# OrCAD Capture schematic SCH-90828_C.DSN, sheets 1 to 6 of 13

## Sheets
1 01 COVER: title: FRDM-MCXN236; rev: C; company: NXP Semiconductors; note: SCH-90828, PDF: SPF-90828; note: 6501 William Cannon Drive West; note: Austin, TX 78735-8598
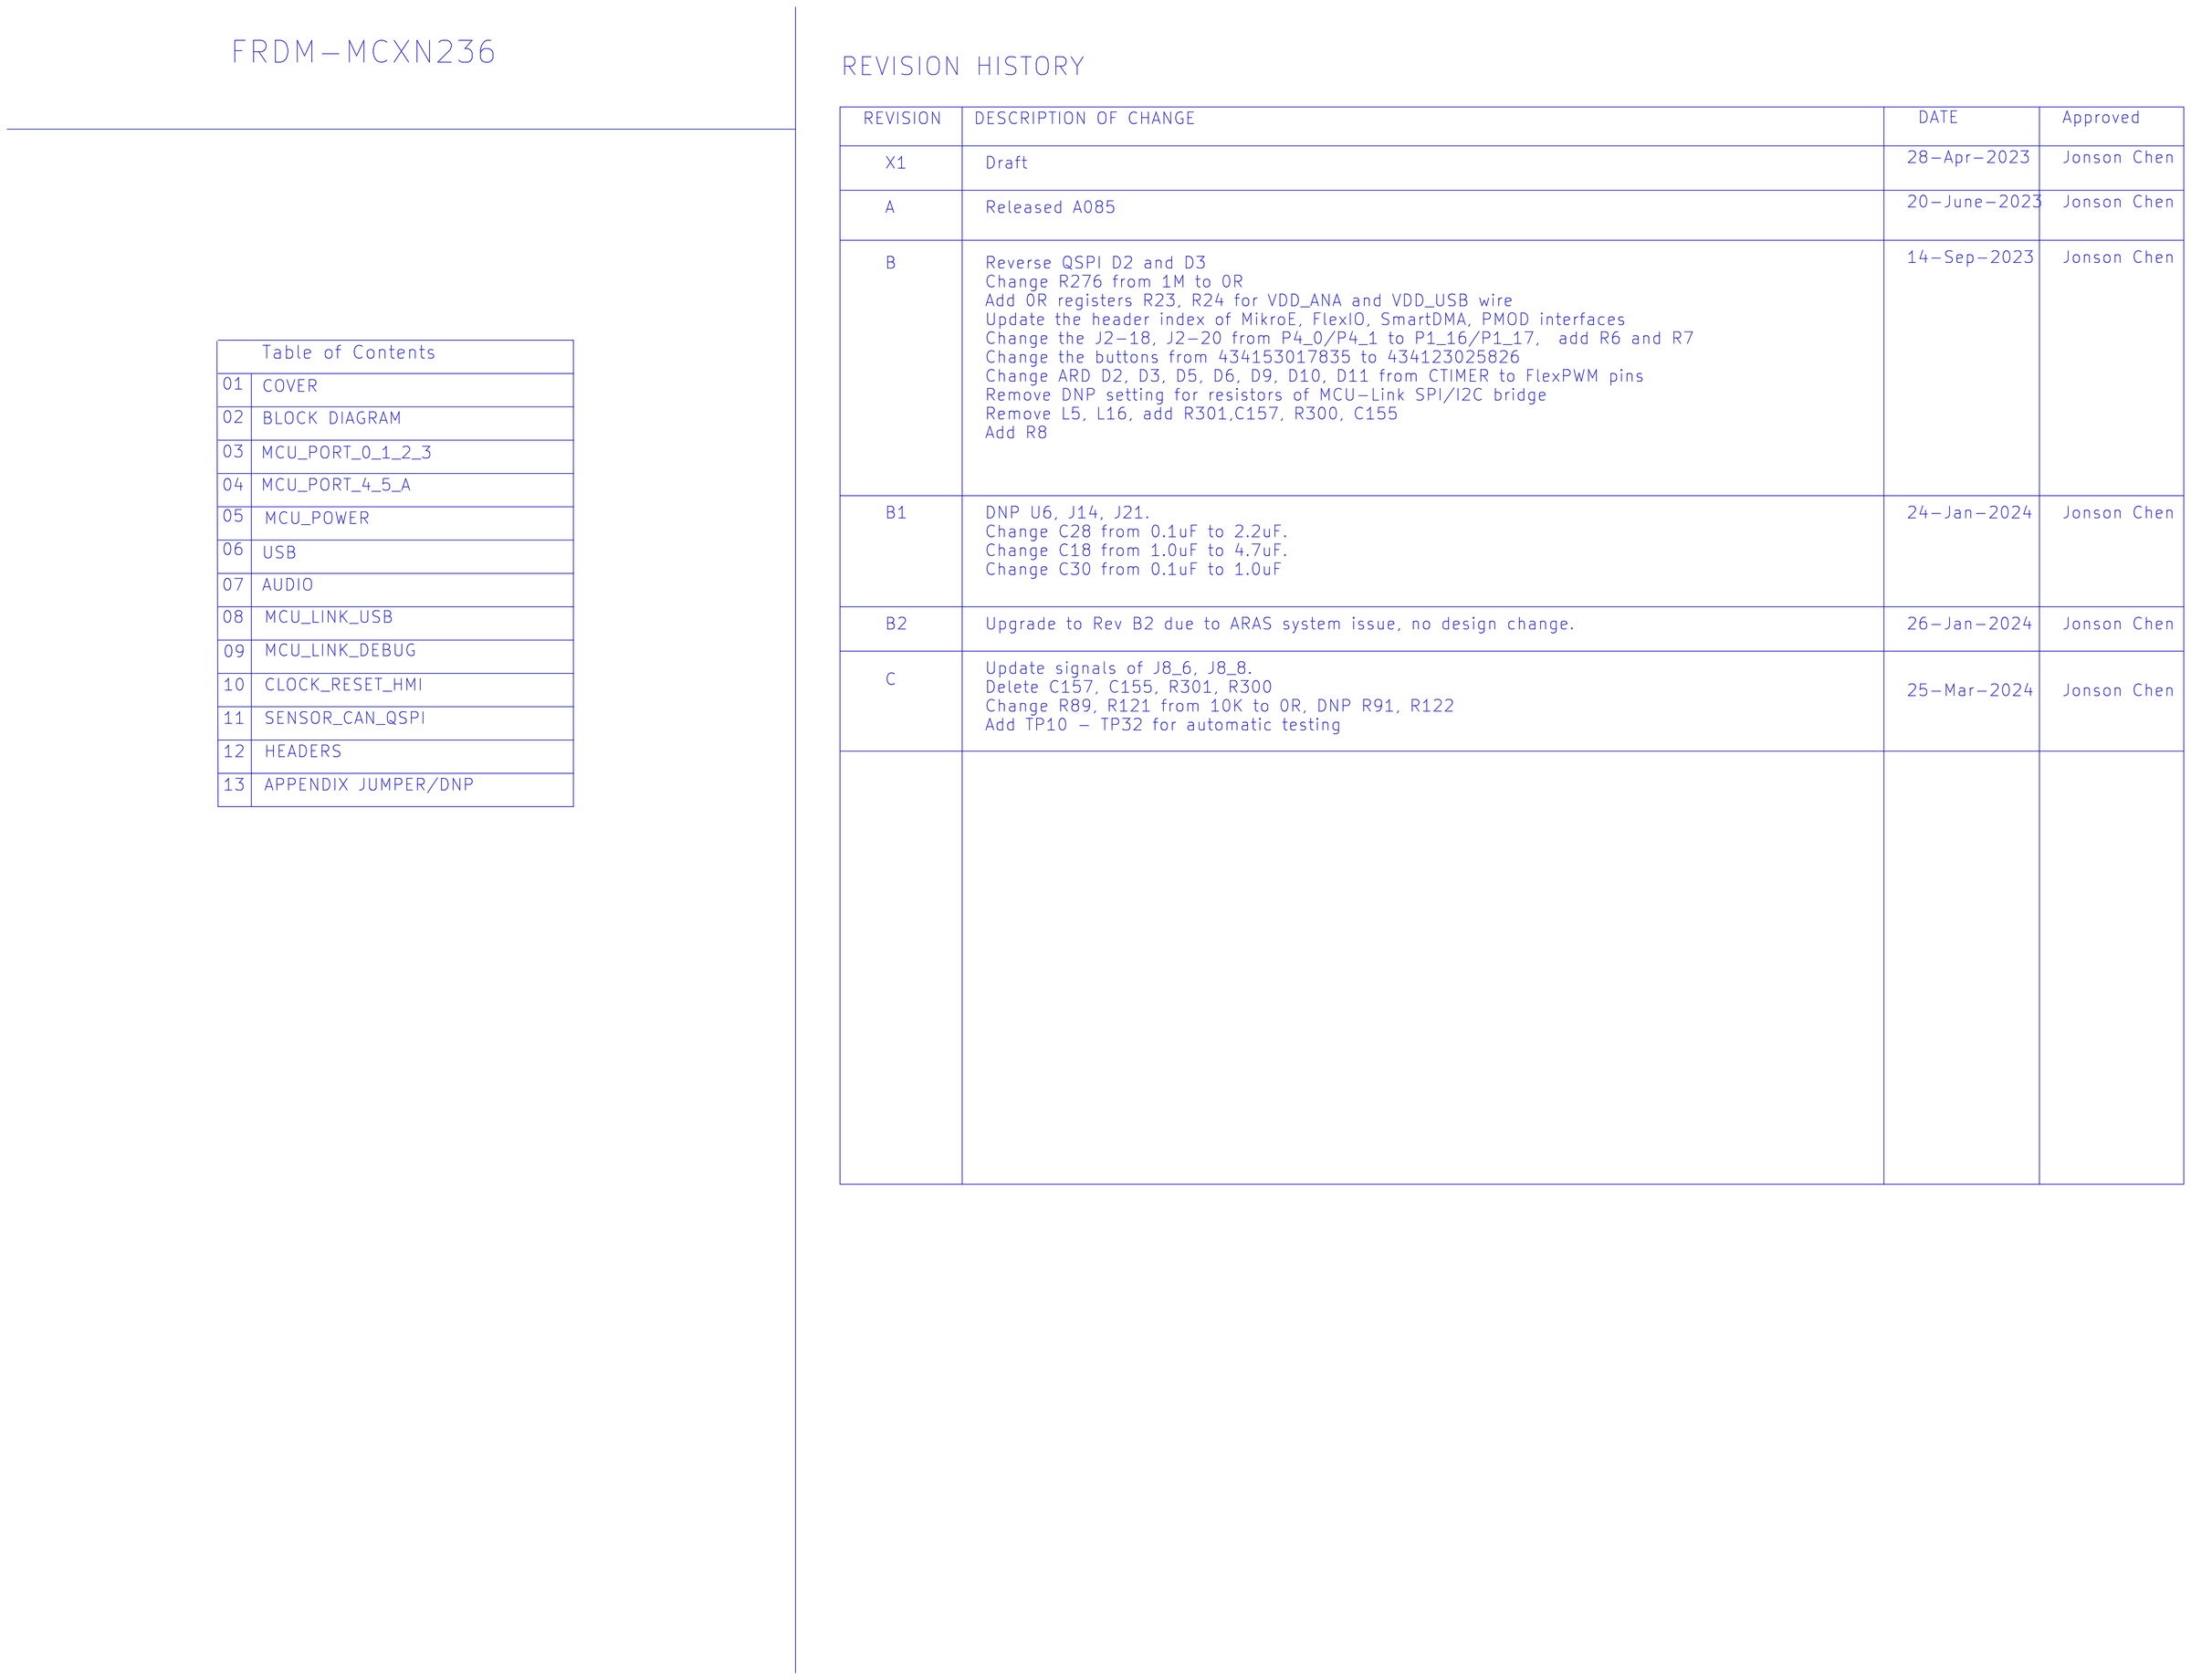
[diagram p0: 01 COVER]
2 02 BLOCK DIAGRAM: note: SCH-90828 PDF: SPF-90828
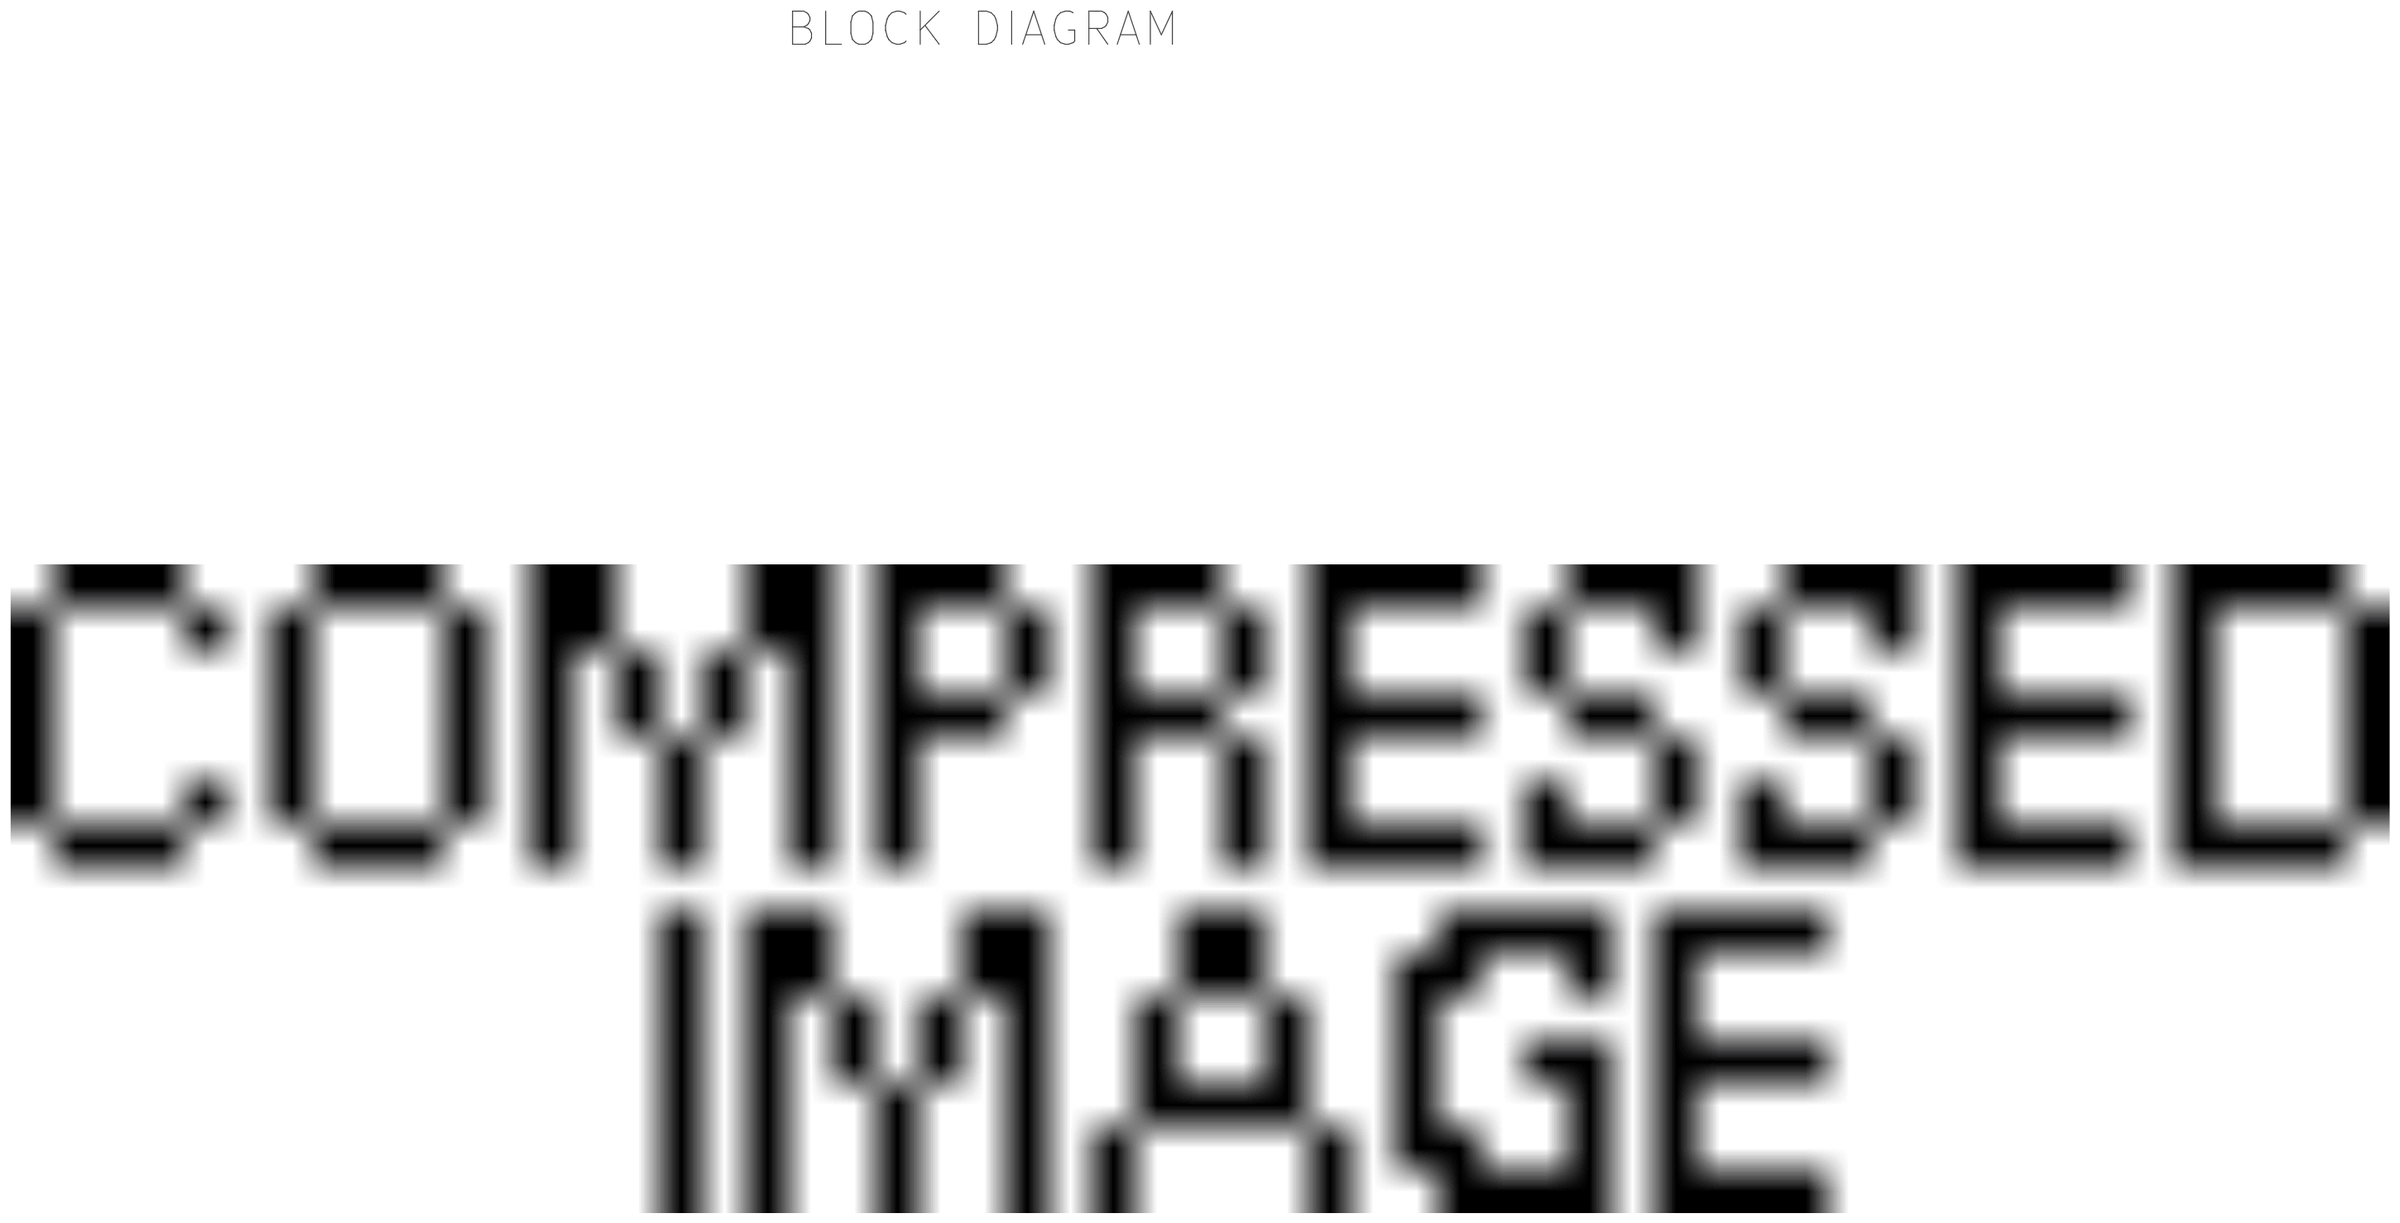
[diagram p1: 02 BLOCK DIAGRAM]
3 03 MCU_PORT_0_1_2_3: size C; note: SCH-90828 PDF: SPF-90828
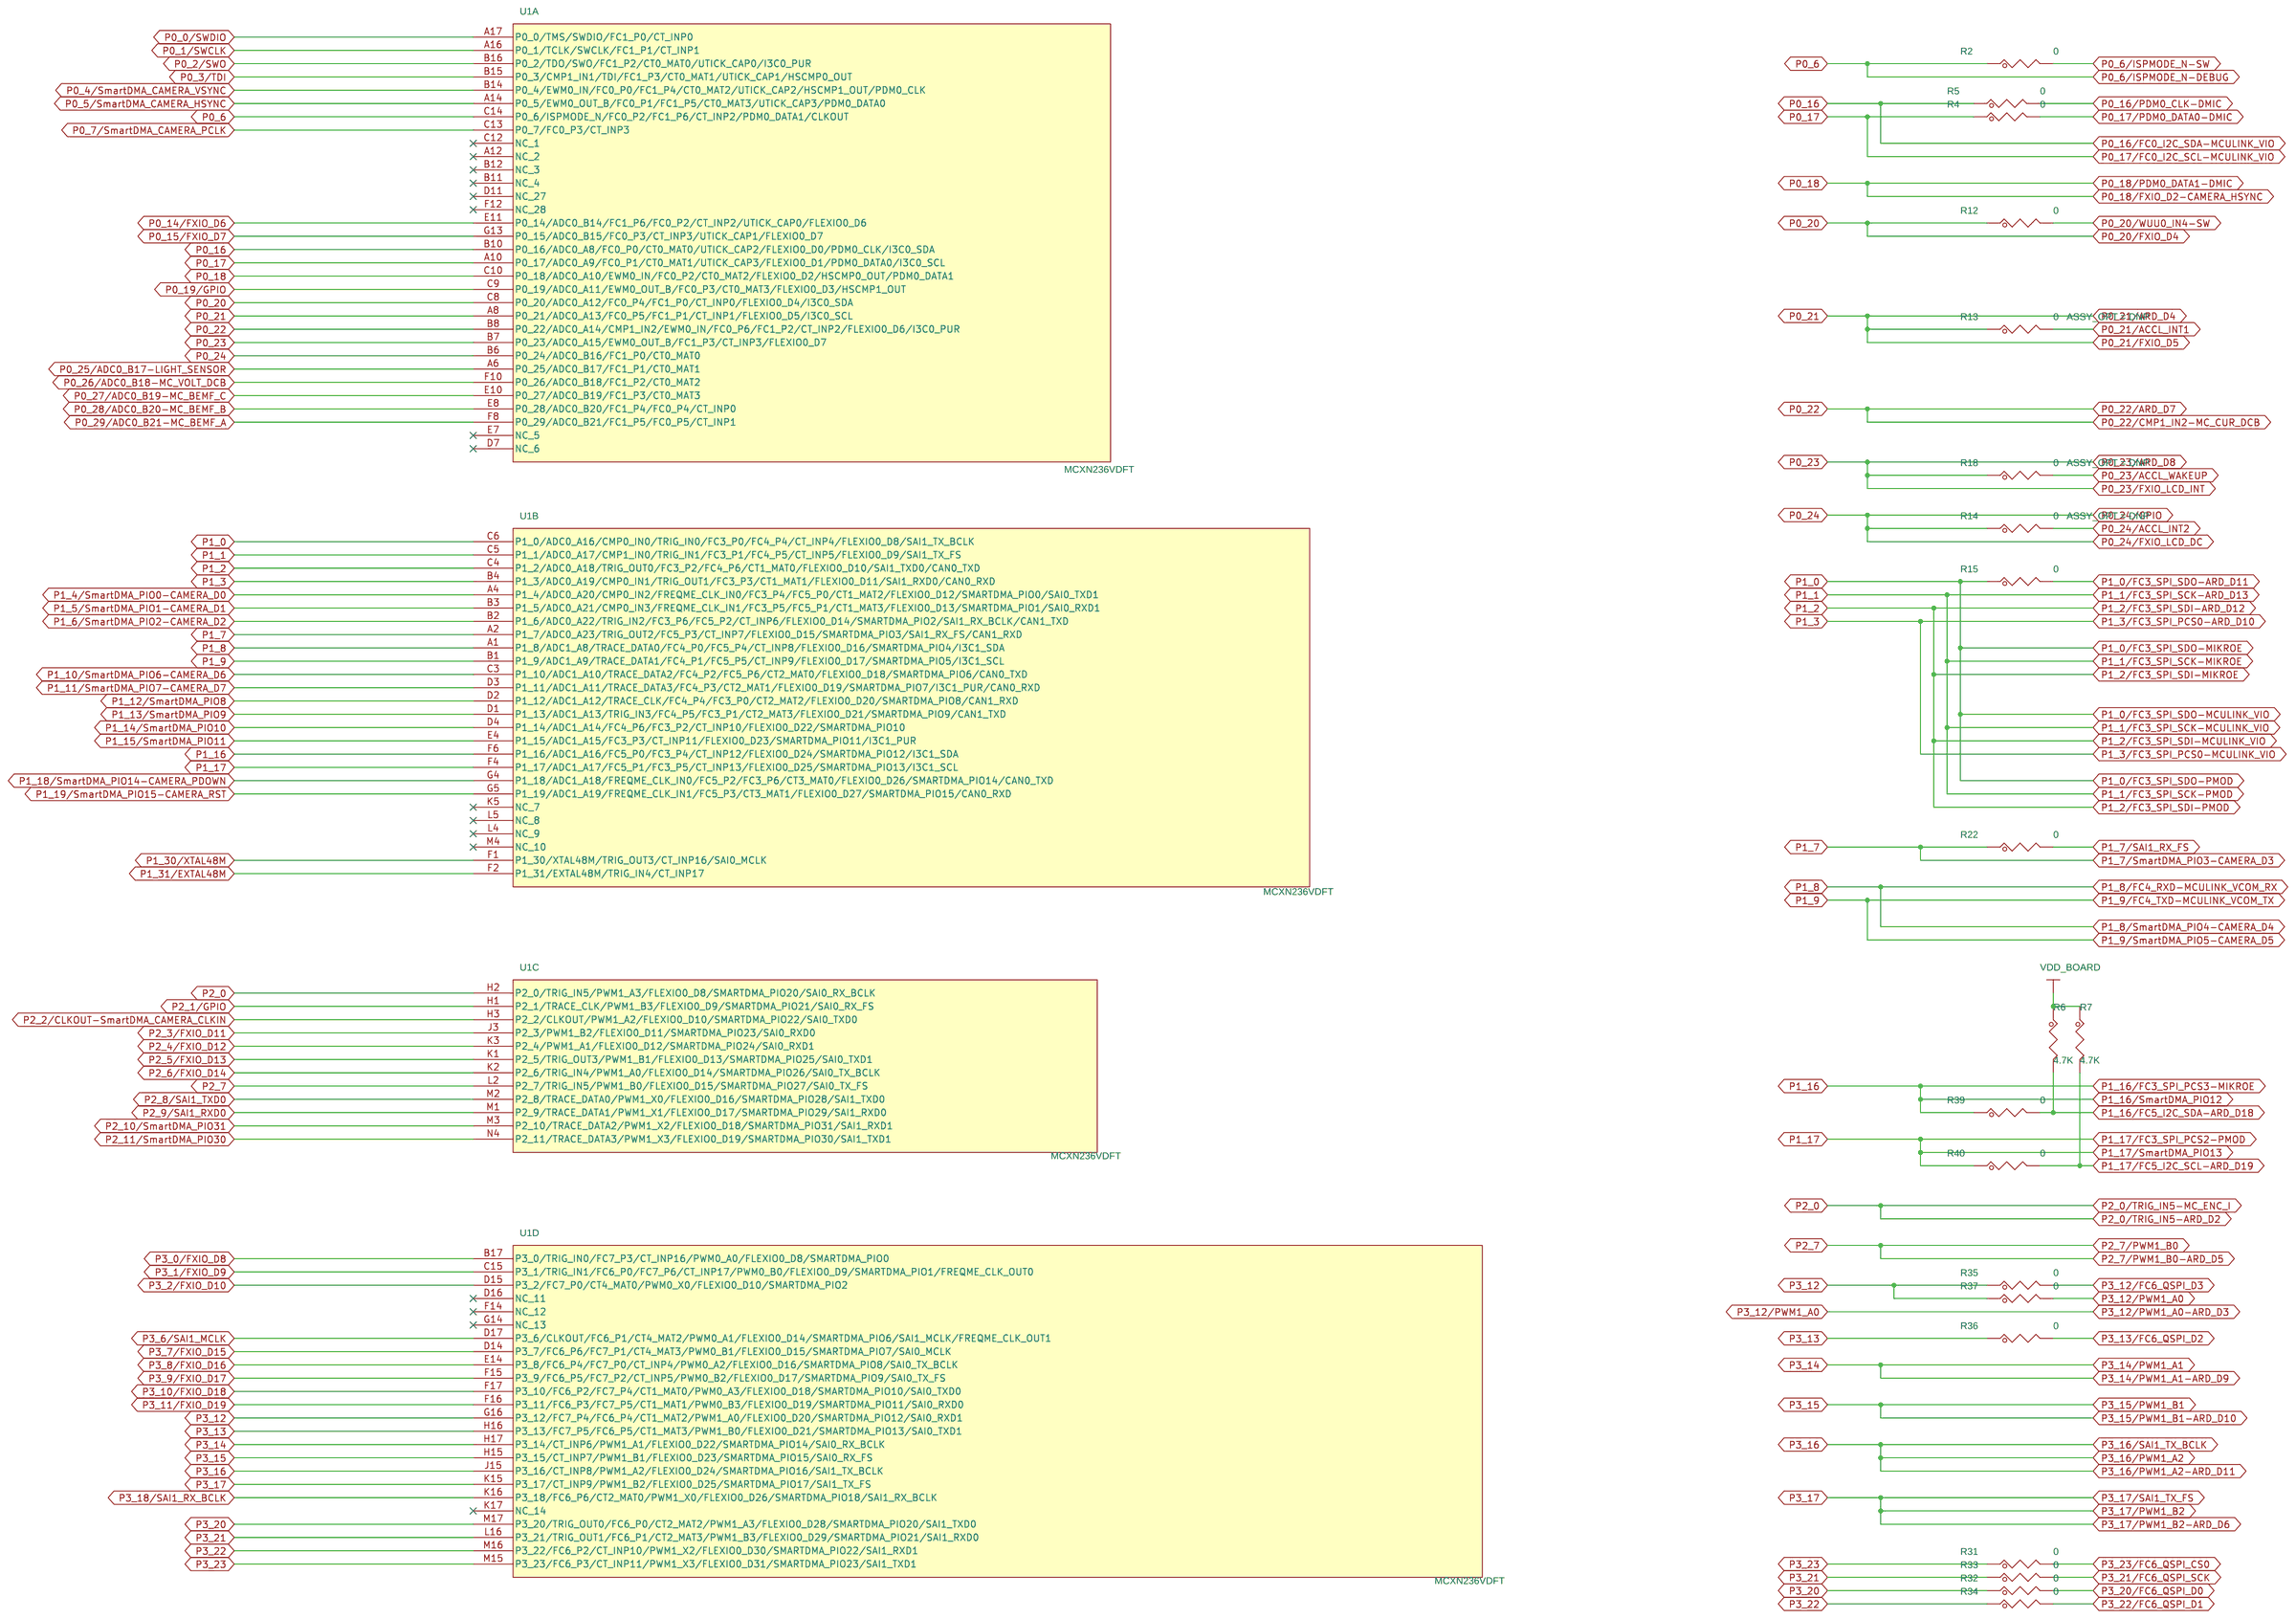
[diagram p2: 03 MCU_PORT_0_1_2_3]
4 04 MCU_PORT_4_5_A: size C; note: SCH-90828 PDF: SPF-90828
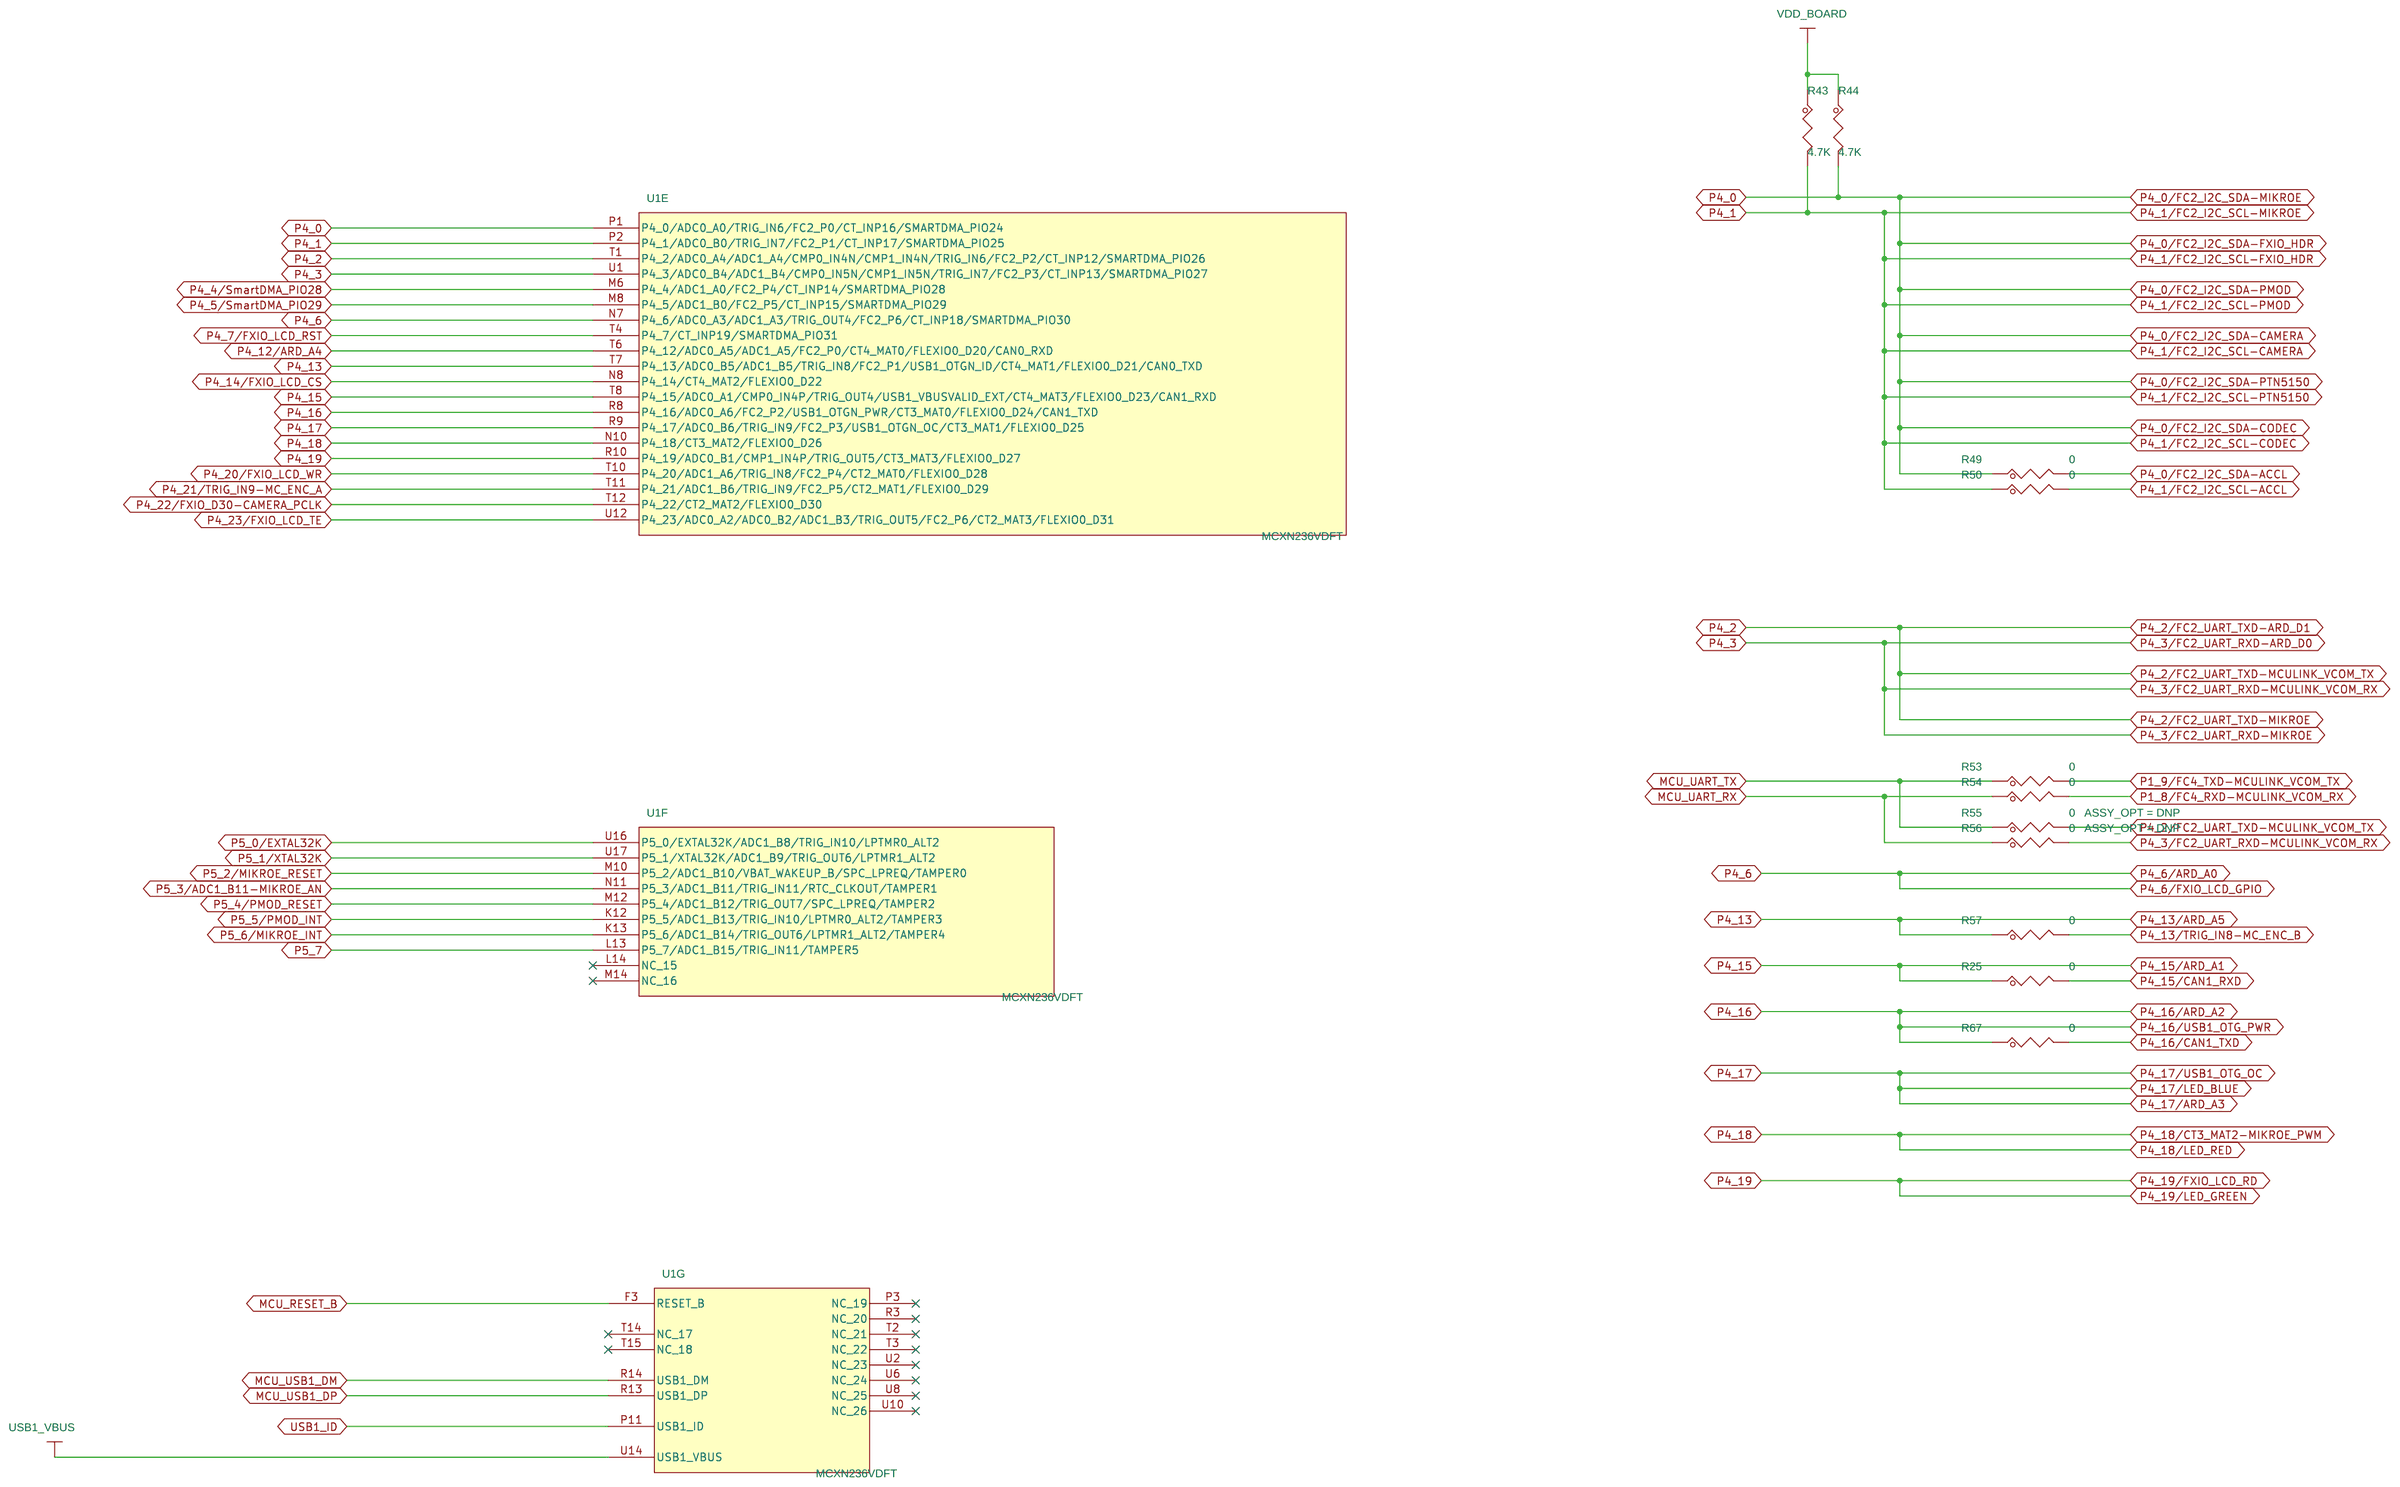
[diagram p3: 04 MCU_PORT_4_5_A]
5 05 MCU_POWER: size C; note: SCH-90828 PDF: SPF-90828
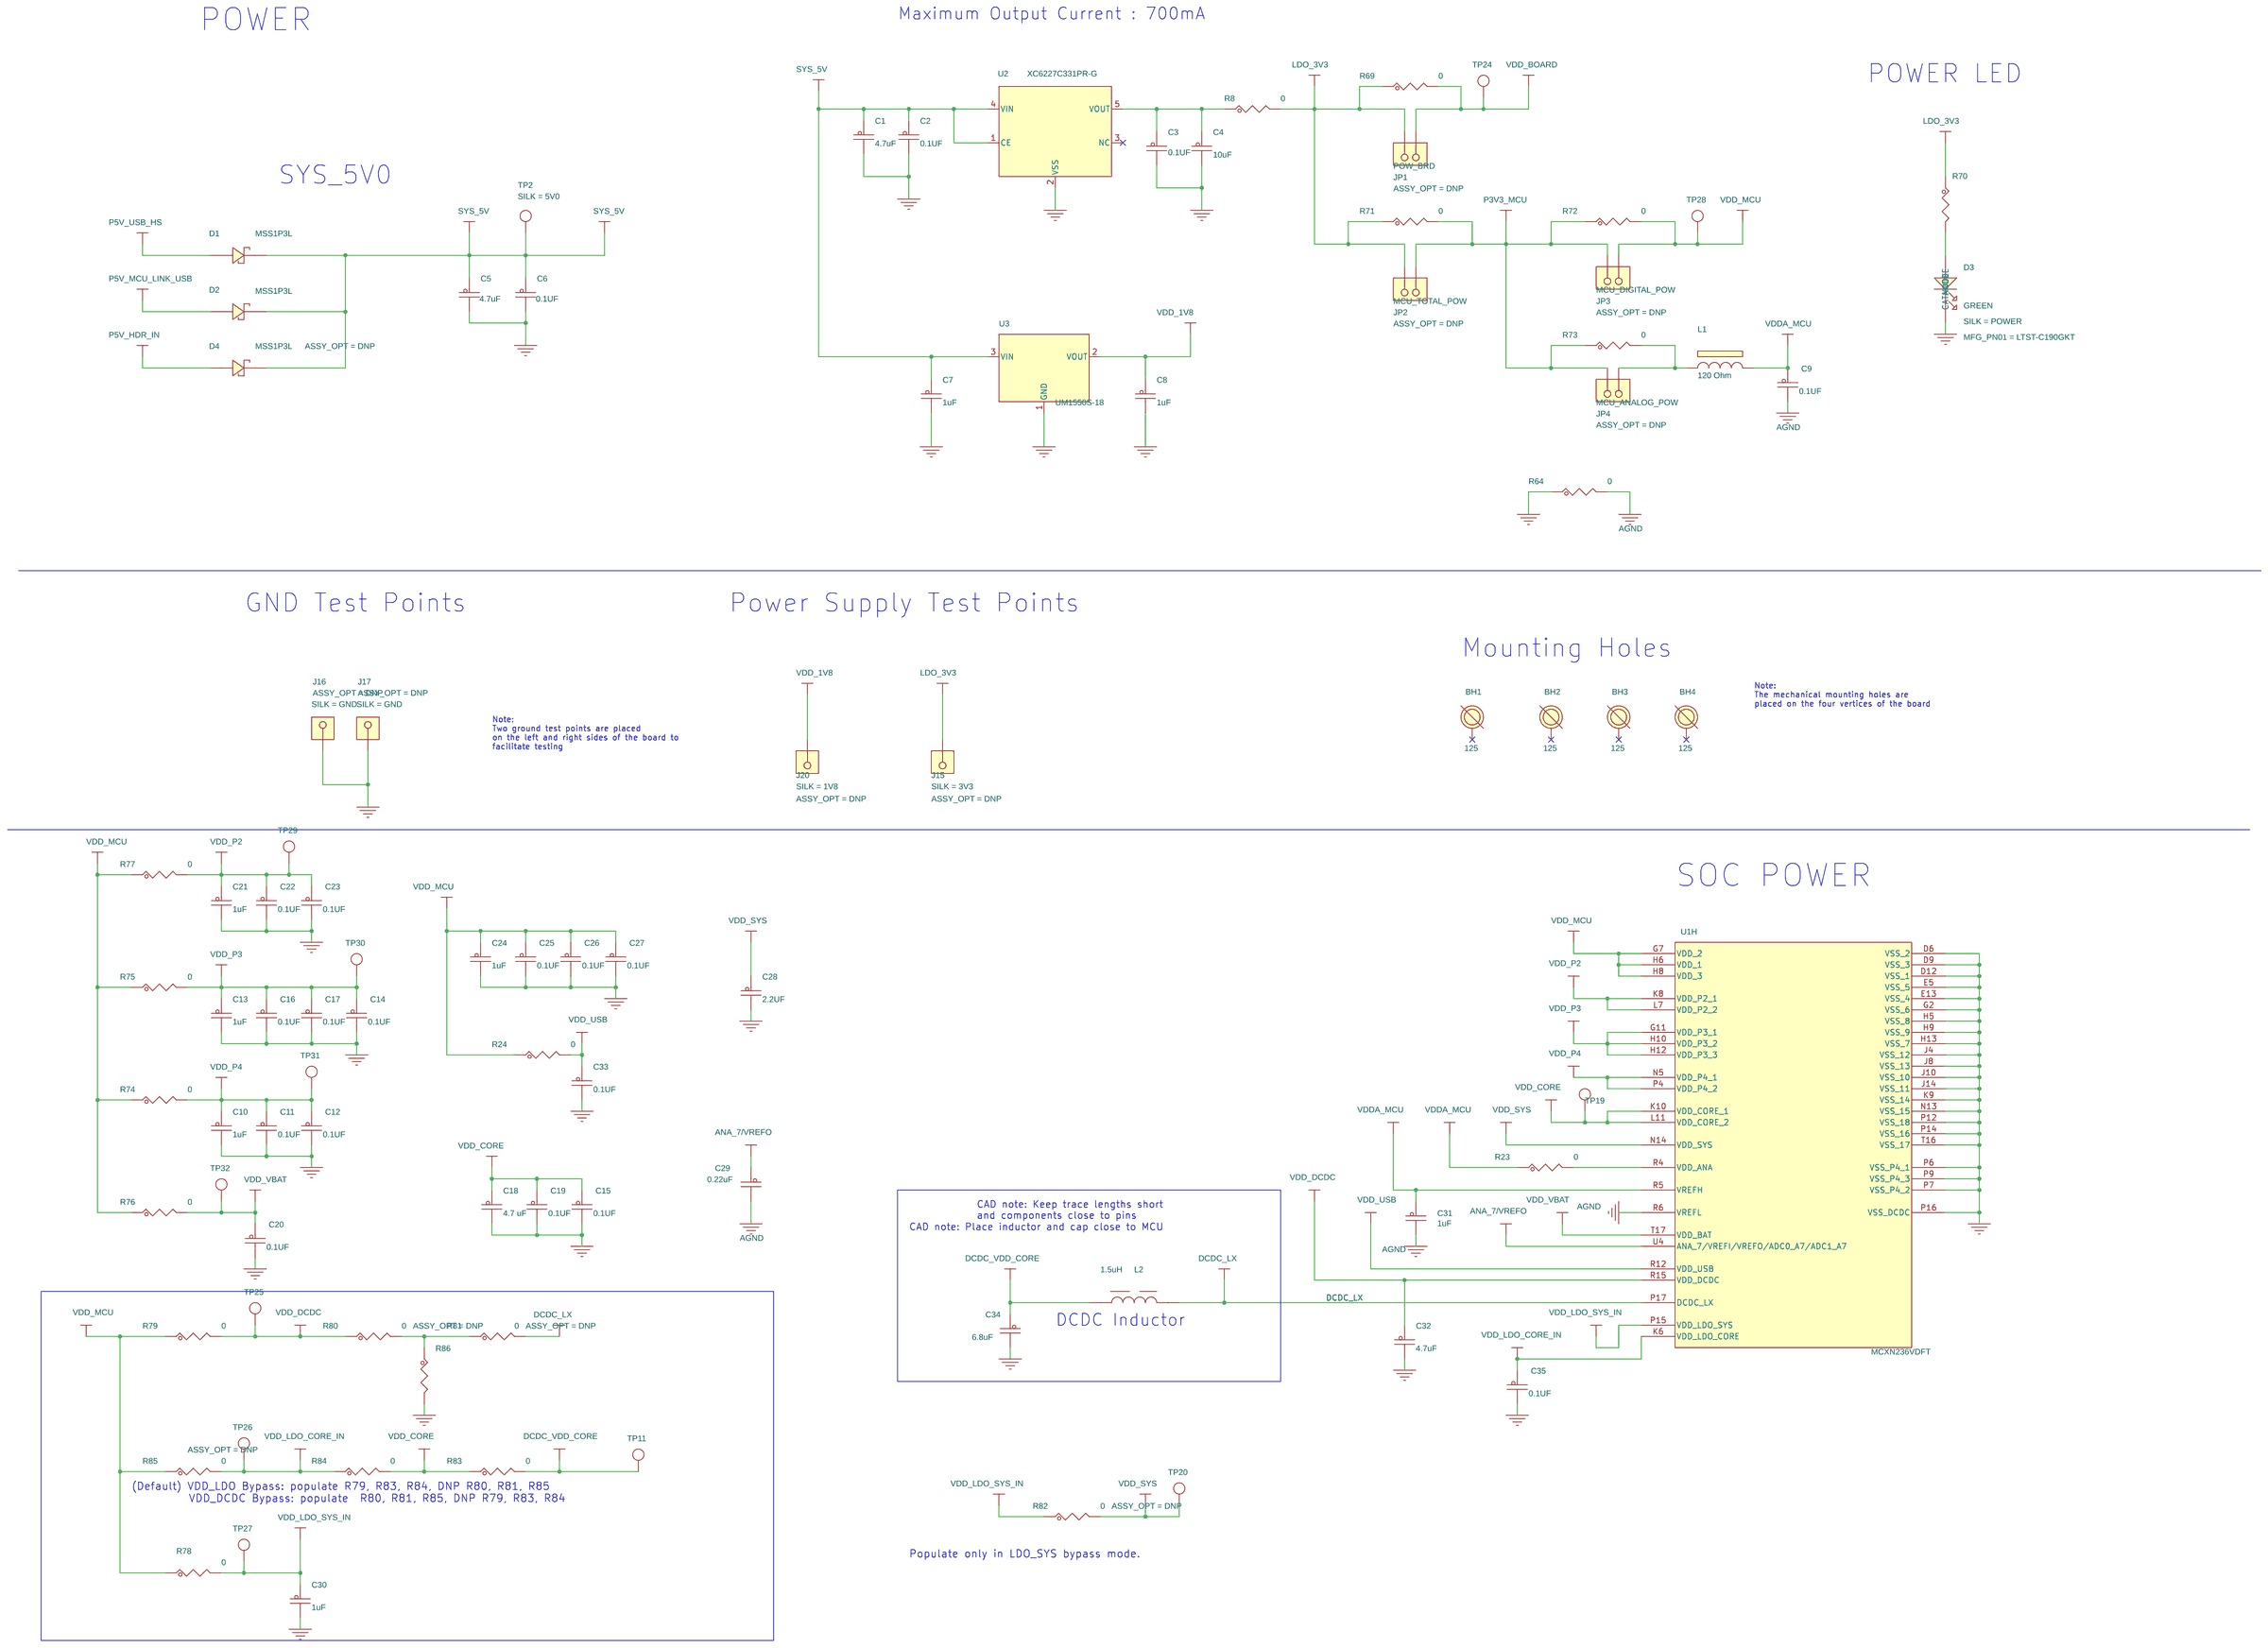
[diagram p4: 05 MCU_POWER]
6 06 USB: size C; note: SCH-90828 PDF: SPF-90828
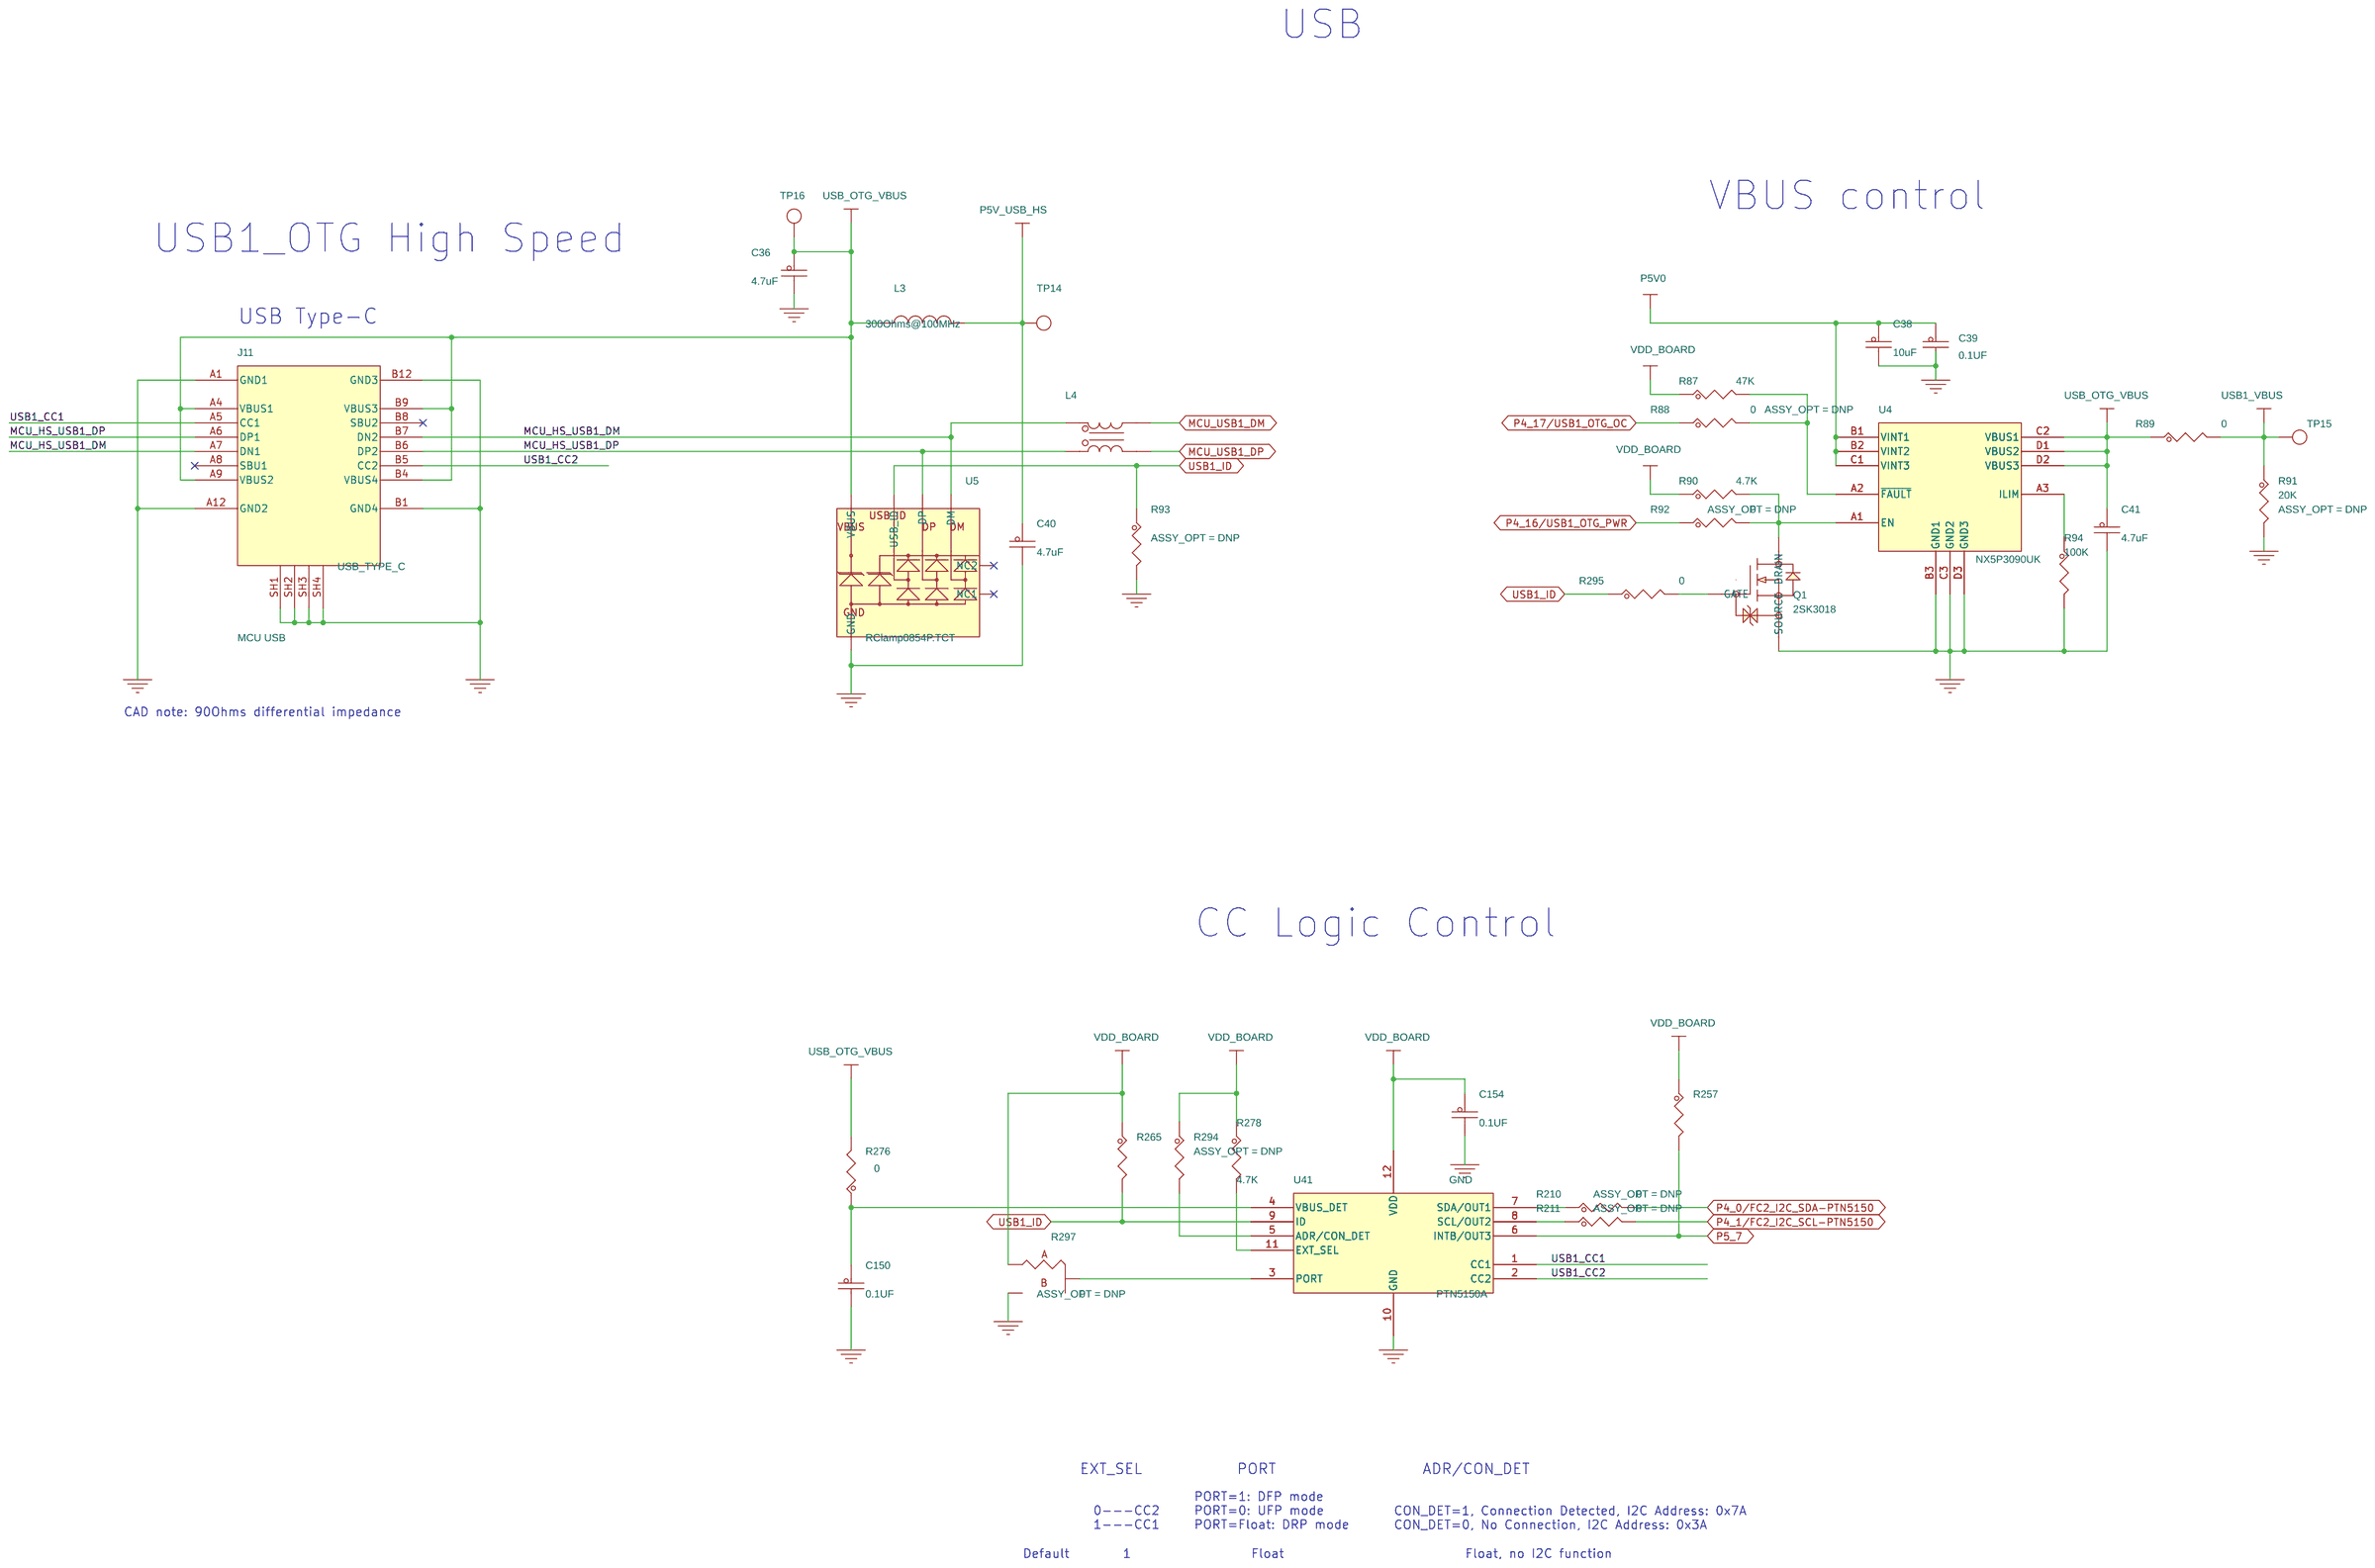
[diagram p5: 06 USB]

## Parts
sheet 03 MCU_PORT_0_1_2_3
R2  0  [RC0402_25]
R4  0  [RC0402_25]
R5  0  [RC0402_25]
R6  4.7K  [RC0402_25]
R7  4.7K  [RC0402_25]
R12  0  [RC0402_25]
R13  0  [RC0402_25]
R14  0  [RC0402_25]
R15  0  [RC0402_25]
R18  0  [RC0402_25]
R22  0  [RC0402_25]
R31  0  [RC0402_25]
R32  0  [RC0402_25]
R33  0  [RC0402_25]
R34  0  [RC0402_25]
R35  0  [RC0402_25]
R36  0  [RC0402_25]
R37  0  [RC0402_25]
R39  0  [RC0402_25]
R40  0  [RC0402_25]
sheet 04 MCU_PORT_4_5_A
R25  0  [RC0402_25]
R43  4.7K  [RC0402_25]
R44  4.7K  [RC0402_25]
R49  0  [RC0402_25]
R50  0  [RC0402_25]
R53  0  [RC0402_25]
R54  0  [RC0402_25]
R55  0  [RC0402_25]
R56  0  [RC0402_25]
R57  0  [RC0402_25]
R67  0  [RC0402_25]
sheet 05 MCU_POWER
BH1  125  [MH125-160]
BH2  125  [MH125-160]
BH3  125  [MH125-160]
BH4  125  [MH125-160]
C1  4.7uF  [CC0603_OV]
C2  0.1UF  [CC0402_25]
C3  0.1UF  [CC0402_25]
C4  10uF  [CC0603_OV]
C5  4.7uF  [CC0603_OV]
C6  0.1UF  [CC0402_25]
C7  1uF  [CC0402_25]
C8  1uF  [CC0402_25]
C9  0.1UF  [CC0402_25]
C10  1uF  [CC0402_25]
C11  0.1UF  [CC0402_25]
C12  0.1UF  [CC0402_25]
C13  1uF  [CC0402_25]
C14  0.1UF  [CC0402_25]
C15  0.1UF  [CC0402_25]
C16  0.1UF  [CC0402_25]
C17  0.1UF  [CC0402_25]
C18  4.7 uF  [cc0402_tol0p15]
C19  0.1UF  [CC0402_25]
C20  0.1UF  [CC0402_25]
C21  1uF  [CC0402_25]
C22  0.1UF  [CC0402_25]
C23  0.1UF  [CC0402_25]
C24  1uF  [CC0402_25]
C25  0.1UF  [CC0402_25]
C26  0.1UF  [CC0402_25]
C27  0.1UF  [CC0402_25]
C28  2.2UF  [CC0402_25]
C29  0.22uF  [CC0402_25]
C30  1uF  [CC0402_25]
C31  1uF  [CC0402_25]
C32  4.7uF  [CC0603_OV]
C33  0.1UF  [CC0402_25]
C34  6.8uF  [CC0603_OV]
C35  0.1UF  [CC0402_25]
D1  MSS1P3L  [smb_2p7x1p4]
D2  MSS1P3L  [smb_2p7x1p4]
D3  GREEN  [LED_0603]
D4  MSS1P3L  [smb_2p7x1p4]
J15  HDR 1X1  [HDR101]
J16  HDR 1X1  [HDR101]
J17  HDR 1X1  [HDR101]
J20  HDR 1X1  [HDR101]
JP1  HDR1X2  [hdr1x2_5p48x2p69]
JP2  HDR1X2  [hdr1x2_5p48x2p69]
JP3  HDR1X2  [hdr1x2_5p48x2p69]
JP4  HDR1X2  [hdr1x2_5p48x2p69]
L1  120 Ohm  [IND_0402]
L2  1.5uH  [ind2_2p7x2p2_1p2_sm]
R8  0  [RC0402_25]
R23  0  [RC0402_25]
R24  0  [RC0402_25]
R64  0  [RC0402_25]
R69  0  [RC0402_25]
R70  470  [RC0402_25]
R71  0  [RC0402_25]
R72  0  [RC0402_25]
R73  0  [RC0402_25]
R74  0  [RC0603_OV]
R75  0  [RC0603_OV]
R76  0  [RC0603_OV]
R77  0  [RC0603_OV]
R78  0  [RC0603_OV]
R79  0  [RC0603_OV]
R80  0  [RC0603_OV]
R81  0  [RC0603_OV]
R82  0  [RC0402_25]
R83  0  [RC0603_OV]
R84  0  [RC0603_OV]
R85  0  [RC0603_OV]
R86  10K  [RC0402_25]
TP2  TPAD_040  [TPAD_040]
TP11  TPAD_040  [TPAD_040]
TP19  TPAD_040  [TPAD_040]
TP20  TPAD_040  [TPAD_040]
TP24  TPAD_040  [TPAD_040]
TP25  TPAD_040  [TPAD_040]
TP26  TPAD_040  [TPAD_040]
TP27  TPAD_040  [TPAD_040]
TP28  TPAD_040  [TPAD_040]
TP29  TPAD_040  [TPAD_040]
TP30  TPAD_040  [TPAD_040]
TP31  TPAD_040  [TPAD_040]
TP32  TPAD_040  [TPAD_040]
U1  MCXN236VDFT  [bga184_0p5_9x9_sm]  (sections A,B,C,D,E,F,G,H)
U2  XC6227C331PR-G  [SOT89-5]
U3  UM1550S-18  [sot23-3-1p95]
sheet 06 USB
C36  4.7uF  [CC0603_OV]
C38  10uF  [CC0603_OV]
C39  0.1UF  [CC0402_25]
C40  4.7uF  [CC0603_OV]
C41  4.7uF  [CC0603_OV]
C150  0.1UF  [CC0402_25]
C154  0.1UF  [CC0402_25]
J11  USB_TYPE_C  [con16_usb_type-c_ra_th]
L3  300Ohms@100MHz  [ind_1p8x1mm_sm]
L4  90OHM  [ind4_choke_0805]
Q1  2SK3018  [SOT323_3]
R87  47K  [RC0402_25]
R88  0  [RC0402_25]
R89  0  [RC0402_25]
R90  4.7K  [RC0402_25]
R91  20K  [RC0402_25]
R92  0  [RC0402_25]
R93  10K  [RC0402_25]
R94  100K  [RC0402_25]
R210  0  [RC0402_25]
R211  0  [RC0402_25]
R257  10K  [0402_CC]
R265  10K  [0402_CC]
R276  0  [RC0402_25]
R278  4.7K  [RC0402_25]
R294  10K  [0402_CC]
R295  0  [RC0402_25]
R297  0  [RC0402_X3]
TP14  TPAD_040  [TPAD_040]
TP15  TPAD_040  [TPAD_040]
TP16  TPAD_040  [TPAD_040]
U4  NX5P3090UK  [wlcsp12_0p4_1p38x1p68mm_smdp]
U5  RClamp0854P.TCT  [slp1616p6]
U41  PTN5150A  [x2qfn12_0p4_1p6x1p6]

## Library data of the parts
R2 R4 R5 R8 R12 R15 R22-R25 R31-R37 R39 R40 R49 R50 R53 R54 R57 R64 R67 R69 R71-R73 R89 R276 R295 = RES: RES MF ZERO OHM 1/10W -- 0402; AGILE_PN: 470-79965; CAD_APPROVED: Yes; FPLIST: RC0402_25,RC0402_HD,RC0402_X2,0402_CC,RC0402_X3; HEIGHT: 0.4; MFG_NAME01: PANASONIC; MFG_PN01: ERJ-2GE0R00X; ROHS: Yes; Temp Range: –55 °C to +155 °C
R6 R7 R43 R44 R90 R278 = RES: RES MF 4.7K OHM 1/16W 1% 0402; AGILE_PN: 470-80911; CAD_APPROVED: Yes; FPLIST: RC0402_25,RC0402_HD,0402_CC; HEIGHT: 0.4; MFG_NAME01: YAGEO; MFG_PN01: RC0402FR-074K7L; ROHS: Yes; Tolerance: 1%
R13 R14 R18 R55 R56 R82 R88 R92 R210 R211 = RES: RES MF ZERO OHM 1/10W -- 0402; AGILE_PN: 470-79965; ASSY_OPT: DNP; CAD_APPROVED: Yes; FPLIST: RC0402_25,RC0402_HD,RC0402_X2,0402_CC,RC0402_X3; HEIGHT: 0.4; MFG_NAME01: PANASONIC; MFG_PN01: ERJ-2GE0R00X; ROHS: Yes; Temp Range: –55 °C to +155 °C
BH1-BH4 = MOUNT_HOLE: NON-PLATED MOUNTING HOLE 125 DRILL / 160 KEEPOUT NO PART TO ORDER; AGILE_PN: 510-75297; CAD_APPROVED: Yes; HEIGHT: 0.1; ROHS: Yes
C1 C5 C32 C36 C40 C41 = CAP_NP: CAP CER 4.7uF 16V 10% X5R 0603; AGILE_PN: 150-80128; CAD_APPROVED: Yes; FPLIST: CC0603_OV,CC0603,0603_CC_NSP; HEIGHT: 0.95; MFG_NAME01: MURATA; MFG_PN01: GRM188R61C475KAAJD; Package Size: 0603; Package Type: SMT; ROHS: Yes; Rated Voltage: 16V; Temp Range: -55C to +85C; Tolerance: 10%
C2 C3 C6 = CAP_NP: CAP CER 0.1UF 16V 10% X7R 0402; 3D_Mechanical_Footprint_File: http://fcl.am.freescale.net/ALLEGRO/step/cc0402_25.STEP; AGILE_PN: 150-75182; CAD_APPROVED: Yes; FPLIST: CC0402_25,CC0402_HD,0402_CC,CAPC0402_L; HEIGHT: 0.635; MFG_NAME01: Samsung Electro-Mechanics; MFG_PN01: CL05B104KO5NNNC; ROHS: Yes; Rated Voltage: 16V; Temp Range: -55C to +125C; Tolerance: 10%
C4 C38 = CAP_NP: CAP CER 10uF 25V 10% X5R 0603; 3D_Mechanical_Footprint_File: http://fcl.am.freescale.net/ALLEGRO/step/cc0603_ov.STEP; AGILE_PN: 150-79569; CAD_APPROVED: Yes; HEIGHT: 1; MFG_NAME01: SANYEAR; MFG_PN01: C0603X5R106K250NT; Package Size: 0603 [1608 Metric]; Package Type: SMD/SMT; ROHS: Yes; Rated Voltage: 25V; Tolerance: 10%
C7 C8 C10 C13 C21 C24 C30 C31 = CAP_NP: CAP CER 1uF 10V 10% X7S 0402; AGILE_PN: 150-80357; CAD_APPROVED: Yes; FPLIST: CC0402_25,CC0402_HD,0402_CC,capc0402_l; HEIGHT: 0.6; MFG_NAME01: MURATA; MFG_PN01: GRM155C71A105KE11D; Package Size: 0402; ROHS: Yes; Rated Voltage: 10V; Temp Range: -55C to +125C; Tolerance: 10%
C9 C11 C12 C14-C17 C19 C20 C22 C23 C25-C27 C33 C35 C150 C154 = CAP_NP: CAP CER 0.1UF 16V 10% X7R 0402; 3D_Mechanical_Footprint_File: http://fcl.am.freescale.net/ALLEGRO/step/cc0402_25.STEP; AGILE_PN: 150-75182; CAD_APPROVED: Yes; FPLIST: CC0402_25,CC0402_HD,0402_CC,CAPC0402_L; HEIGHT: 0.635; MFG_NAME01: Samsung Electro-Mechanics; MFG_PN01: CL05B104KO5NNNC; ROHS: Yes; Rated Voltage: 16V; SIGNAL_MODEL: DEFAULT_CAPACITOR_100000pF_2_1; TOL: 10%; Temp Range: -55C to +125C; Temp_Range: -55°C to +85°C; Tolerance: 10%; VOLTAGE: 16V
C18 = CAP_NP: CAP CER 4.7uF 10V 20% X5R 0402; 3D_Mechanical_Footprint_File: http://fcl.am.freescale.net/ALLEGRO/step/cc0402_tol0p15.STEP; AGILE_PN: TMP-CIP-16501; CAD_APPROVED: Yes; FPLIST: cc0402_tol0p15,cc0402_tol0p15_ov; HEIGHT: 0.65; MFG_NAME01: SAMSUNG ELECTRO MECHANICS; MFG_PN01: CL05A475MP5NRNC; PRE_APN: 150-10035; ROHS: Yes; Rated Voltage: 10V; Temp Range: -55C to +85C; Tolerance: 20%
C28 = CAP_NP: CAP CER 2.2UF 10V 20% X5R 0402; 3D_Mechanical_Footprint_File: http://fcl.am.freescale.net/ALLEGRO/step/cc0402_25.STEP; AGILE_PN: 150-79665; CAD_APPROVED: Yes; FPLIST: CC0402_25,CC0402_HD,0402_CC,capc0402_l; HEIGHT: 0.55; MFG_NAME01: KEMET; MFG_PN01: C0402C104M3PAC7867; ROHS: Yes; Rated Voltage: 10V; Temp Range: -55C to +85C; Tolerance: 20%; VOLTAGE: 10V
C29 = CAP_NP: CAP CER 0.22UF 16V 10% X7R 0402; 3D_Mechanical_Footprint_File: http://fcl.am.freescale.net/ALLEGRO/step/cc0402_25.STEP; AGILE_PN: 150-78886; CAD_APPROVED: Yes; FPLIST: CC0402_25,CC0402_HD,0402_CC; HEIGHT: 0.55; MFG_NAME01: FENGHUA; MFG_PN01: 0402B224K160NT; Package Size: 0402 [1005 Metric]; Package Type: SMD/SMT; ROHS: Yes; Rated Voltage: 16V; Temp Range: -55C to +125C; Tolerance: 10%; VOLTAGE: 16V
C34 = CAP_NP: CAP CER 6.8uF 6.3V 10% X7S 0603; AGILE_PN: 150-79711; CAD_APPROVED: Yes; FPLIST: CC0603_OV,CC0603,0603_CC; HEIGHT: 1; MFG_NAME01: TDK; MFG_PN01: C1608X7S0J685K080AC; Package Size: 0603; Package Type: Reel; ROHS: Yes; Rated Voltage: 6.3V; Temp Range: -55C to +125C; Tolerance: 10%; VOLTAGE: 6.3V
D1 D2 = DIODE_SCHTKY: DIODE SCH 1A 30V MICROSMP SMT; 3D_Mechanical_Footprint_File: http://fcl.am.freescale.net/ALLEGRO/step/smb_2p7x1p4.step; AGILE_PN: 480-76978; CAD_APPROVED: Yes; HEIGHT: 0.73; MFG_NAME01: VISHAY INTERTECHNOLOGY; MFG_PN01: MSS1P3L-M3/89A; Rated Voltage: 30V
D3 = LED: LED GREEN GAP ON GAP SM 0603; AGILE_PN: 370-75088; CAD_APPROVED: Yes; HEIGHT: 0.80; MFG_NAME01: LITE ON; MFG_PN01: LTST-C190GKT; SILK: POWER
D4 = DIODE_SCHTKY: DIODE SCH 1A 30V MICROSMP SMT; 3D_Mechanical_Footprint_File: http://fcl.am.freescale.net/ALLEGRO/step/smb_2p7x1p4.step; AGILE_PN: 480-76978; ASSY_OPT: DNP; CAD_APPROVED: Yes; HEIGHT: 0.73; MFG_NAME01: VISHAY INTERTECHNOLOGY; MFG_PN01: MSS1P3L-M3/89A; Rated Voltage: 30V
J15 = CONN_HDR_1X1: HDR 1X1 TH -- 330H AU 100L; 3D_Mechanical_Footprint_File: http://fcl.am.freescale.net/ALLEGRO/step/hdr101.STEP; AGILE_PN: 210-75767; ASSY_OPT: DNP; CAD_APPROVED: Yes; HEIGHT: 8.585; MFG_NAME01: SAMTEC; MFG_PN01: HTSW-101-07-SM-S; Package Size: 2.54 x 2.54 mm; ROHS: Yes; SILK: 3V3
J16 J17 = CONN_HDR_1X1: HDR 1X1 TH -- 330H AU 100L; 3D_Mechanical_Footprint_File: http://fcl.am.freescale.net/ALLEGRO/step/hdr101.STEP; AGILE_PN: 210-75767; ASSY_OPT: DNP; CAD_APPROVED: Yes; HEIGHT: 8.585; MFG_NAME01: SAMTEC; MFG_PN01: HTSW-101-07-SM-S; Package Size: 2.54 x 2.54 mm; ROHS: Yes; SILK: GND
J20 = CONN_HDR_1X1: HDR 1X1 TH -- 330H AU 100L; 3D_Mechanical_Footprint_File: http://fcl.am.freescale.net/ALLEGRO/step/hdr101.STEP; AGILE_PN: 210-75767; ASSY_OPT: DNP; CAD_APPROVED: Yes; HEIGHT: 8.585; MFG_NAME01: SAMTEC; MFG_PN01: HTSW-101-07-SM-S; Package Size: 2.54 x 2.54 mm; ROHS: Yes; SILK: 1V8
JP1 = CONN_HDR_2X1: HDR 1X2 TH 100MIL SP 342H AU 118L; 3D_Mechanical_Footprint_File: http://fcl.am.freescale.net/ALLEGRO/step/hdr1x2_5p48x2p69.STEP; AGILE_PN: 210-80468; ASSY_OPT: DNP; CAD_APPROVED: Yes; HEIGHT: 8.69; MFG_NAME01: WURTH ELEKTRONIK EISOS GMBH & CO. KG (ELECTRONIC & ELECTROMEHANICAL COMP); MFG_PN01: 61300211121; Package Type: TH; ROHS: Yes; SILK: POW_BRD; Temp Range: -40°C to 105°C
JP2 = CONN_HDR_2X1: HDR 1X2 TH 100MIL SP 342H AU 118L; 3D_Mechanical_Footprint_File: http://fcl.am.freescale.net/ALLEGRO/step/hdr1x2_5p48x2p69.STEP; AGILE_PN: 210-80468; ASSY_OPT: DNP; CAD_APPROVED: Yes; HEIGHT: 8.69; MFG_NAME01: WURTH ELEKTRONIK EISOS GMBH & CO. KG (ELECTRONIC & ELECTROMEHANICAL COMP); MFG_PN01: 61300211121; Package Type: TH; ROHS: Yes; SILK: MCU_TOTAL_POW; Temp Range: -40°C to 105°C
JP3 = CONN_HDR_2X1: HDR 1X2 TH 100MIL SP 342H AU 118L; 3D_Mechanical_Footprint_File: http://fcl.am.freescale.net/ALLEGRO/step/hdr1x2_5p48x2p69.STEP; AGILE_PN: 210-80468; ASSY_OPT: DNP; CAD_APPROVED: Yes; HEIGHT: 8.69; MFG_NAME01: WURTH ELEKTRONIK EISOS GMBH & CO. KG (ELECTRONIC & ELECTROMEHANICAL COMP); MFG_PN01: 61300211121; Package Type: TH; ROHS: Yes; SILK: MCU_DIGITAL_POW; Temp Range: -40°C to 105°C
JP4 = CONN_HDR_2X1: HDR 1X2 TH 100MIL SP 342H AU 118L; 3D_Mechanical_Footprint_File: http://fcl.am.freescale.net/ALLEGRO/step/hdr1x2_5p48x2p69.STEP; AGILE_PN: 210-80468; ASSY_OPT: DNP; CAD_APPROVED: Yes; HEIGHT: 8.69; MFG_NAME01: WURTH ELEKTRONIK EISOS GMBH & CO. KG (ELECTRONIC & ELECTROMEHANICAL COMP); MFG_PN01: 61300211121; Package Type: TH; ROHS: Yes; SILK: MCU_ANALOG_POW; Temp Range: -40°C to 105°C
L1 = INDUCTOR_FERRITE: IND FER BEAD 120 OHM@100MHZ 0.5A 25% 0402; AGILE_PN: 180-77771; CAD_APPROVED: Yes; FPLIST: IND_0402,0402_CC; HEIGHT: 0.55; MFG_NAME01: MURATA; MFG_PN01: BLM15AG121SN1D; Package Size: 0402; ROHS: Yes
L2 = INDUCTOR_B: IND PWR 1.5uH@1MHz 1.8A 0.065OHM 20% AEC-Q200 SMT; 3D_Mechanical_Footprint_File: http://fcl.am.freescale.net/ALLEGRO/step/ind2_2p7x2p2_1p2_sm.step; AGILE_PN: 180-80401; CAD_APPROVED: YES; HEIGHT: 1.2; MFG_NAME01: WURTH ELEKTRONIK EISOS GMBH & CO. KG (ELECTRONIC & ELECTROMEHANICAL COMP); MFG_PN01: 74404024015; Package Size: 2512; ROHS: Yes; Temp Range: -40C to +125C
R70 = RES: RES MF 470 OHM 1/16W 1% 0402; AGILE_PN: 470-76469; CAD_APPROVED: Yes; FPLIST: RC0402_25,RC0402_HD,0402_CC; HEIGHT: 0.4; MFG_NAME01: THYE MING TECH CO LTD; MFG_PN01: CR-02FL6--470R; ROHS: Yes; SIGNAL_MODEL: DEFAULT_RESISTOR_430.000000OHM_2_1; TOL: 1%; Temp_Range: -55&#8451; to 155&#8451;; Tolerance: 1%; VOLTAGE: 50V
R74-R78 R83 R84 = RES: RES MF ZERO OHM 1/10W -- 0603; AGILE_PN: 470-80866; CAD_APPROVED: Yes; FPLIST: RC0603_OV,RC0603,R603-X2,r603-x2_b,0603_CC,IND_0603HP_NSP,CC0603_OV_NSP; HEIGHT: 0.6; MFG_NAME01: YAGEO AMERICA; MFG_PN01: RC0603FR-070RL; ROHS: Yes; Temp Range: –55 °C to +155 °C
R79 = RES: RES MF ZERO OHM 1/10W -- 0603; AGILE_PN: 470-80866; CAD_APPROVED: Yes; FPLIST: RC0603_OV,RC0603,R603-X2,r603-x2_b,0603_CC,IND_0603HP_NSP,CC0603_OV_NSP; HEIGHT: 0.6MM; MFG_NAME01: YAGEO AMERICA; MFG_PN01: RC0603FR-070RL; ROHS: Yes; Temp Range: –55 °C to +155 °C
R80 R81 R85 = RES: RES MF ZERO OHM 1/10W -- 0603; AGILE_PN: 470-80866; ASSY_OPT: DNP; CAD_APPROVED: Yes; FPLIST: RC0603_OV,RC0603,R603-X2,r603-x2_b,0603_CC,IND_0603HP_NSP,CC0603_OV_NSP; HEIGHT: 0.6; MFG_NAME01: YAGEO AMERICA; MFG_PN01: RC0603FR-070RL; ROHS: Yes; Temp Range: –55 °C to +155 °C
R86 = RES: RES MF 10K 1/16W 5% 0402; AGILE_PN: 470-75557; CAD_APPROVED: Yes; FPLIST: RC0402_25,RC0402_HD,0402_CC; HEIGHT: 0.4; MFG_NAME01: BOURNS; MFG_PN01: CR0402-JW-103GLF; ROHS: NULL; Tolerance: 5%
TP2 = TestLoop: TEST POINT PAD 40MIL DIA SMT, NO PART TO ORDER; AGILE_PN: 211-76643; CAD_APPROVED: Yes; HEIGHT: 0.1; MFG_NAME01: NOTACOMPONENT; MFG_PN01: NOTACOMPONENT; ROHS: Yes; SILK: 5V0
TP11 TP14-TP16 TP19 TP20 TP24-TP32 = TestLoop: TEST POINT PAD 40MIL DIA SMT, NO PART TO ORDER; AGILE_PN: 211-76643; CAD_APPROVED: Yes; HEIGHT: 0.1; MFG_NAME01: NOTACOMPONENT; MFG_PN01: NOTACOMPONENT; ROHS: Yes
U1 = MCXN236VDFT_BGA184_B: IC MCU LOW POWER 150MHz ARM Nirvana Nx5x -- VFBGA184; 3D_Mechanical_Footprint_File: http://fcl.am.freescale.net/ALLEGRO/step/bga184_0p5_9x9_sm.STEP; AGILE_PN: TMP-CIP-14239; CAD_APPROVED: Yes; HEIGHT: 0.98 mm; MFG_NAME01: NXP SEMICONDUCTORS; PRE_APN: 344-78012; Package Size: 9*9; ROHS: Yes; Temp Range: -40 °C to +105 °C
U2 = XC6227C_5P: IC VREG LDO  3.3V 0.7A 1.7-6.0V SOT-89-5; AGILE_PN: 315-80827; CAD_APPROVED: Yes; HEIGHT: 1.6; MFG_NAME01: TOREX; ROHS: Yes; VOLTAGE: 1.7V ~ 6.0V
U3 = MCP1700: IC LIN VREG LDO 1.8V 250MA 1.8-8V SOT23-3; AGILE_PN: 315-81422; CAD_APPROVED: Yes; HEIGHT: 1.4; MFG_NAME01: UNION SEMICONDUCTOR, INC; ROHS: Yes; VOLTAGE: 1.8-8V
C39 = CAP_NP: CAP CER 0.1UF 16V 10% X7R 0402; 3D_Mechanical_Footprint_File: http://fcl.am.freescale.net/ALLEGRO/step/cc0402_25.STEP; AGILE_PN: 150-75182; CAD_APPROVED: Yes; FPLIST: CC0402_25,CC0402_HD,0402_CC,CAPC0402_L; HEIGHT: 0.635; MFG_NAME01: Samsung Electro-Mechanics; MFG_PN01: CL05B104KO5NNNC; ROHS: Yes; Rated Voltage: 16V; Temp Range: -55C to +125C; Tolerance: 10%; VOLTAGE: 16V
J11 = USB16_TYPEC_4SH: CON 2X8 USB2.0_TYPE_C RCPT 0.85MM 144H AU 63L; AGILE_PN: 210-82931; CAD_APPROVED: Yes; HEIGHT: 3.66; MFG_NAME01: GCT; MFG_PN01: USB4085-GF-A; Package Type: Through Hole, Right Angle; ROHS: Yes; SILK: MCU USB; Temp Range: -40 °C to +85 °C
L3 = INDUCTOR: IND FER BEAD 300Ohms@100MHz 2A 25% 0603; 3D_Mechanical_Footprint_File: http://fcl.am.freescale.net/ALLEGRO/step/ind_1p8x1mm_sm.step; AGILE_PN: 180-78959; CAD_APPROVED: Yes; HEIGHT: 1; MFG_NAME01: WURTH ELEKTRONIK EISOS GMBH & CO. KG (ELECTRONIC & ELECTROMEHANICAL COMP); MFG_PN01: 742792641; Package Size: 0603; ROHS: Yes; Temp Range: -55°C to 125°C
L4 = DLW43: IND CHK 90 OHM@100MHZ 330MA 25% 0805; 3D_Mechanical_Footprint_File: http://fcl.am.freescale.net/ALLEGRO/step/ind4_choke_0805_39h.STEP; AGILE_PN: 180-76336; CAD_APPROVED: Yes; HEIGHT: 1; MFG_NAME01: MURATA; MFG_PN01: DLW21HN900SQ2L; PART_TYPE: CHOKE; ROHS: Yes; Temp Range: -40°C to +85°C; Tolerance: 25%
Q1 = 2SK3018: TRANS MOSFET N-CH 30V .1A SOT-323; AGILE_PN: 480-75317; CAD_APPROVED: Yes; HEIGHT: 0.9; MFG_NAME01: ROHM; MFG_PN01: 2SK3018T106; ROHS: Yes
R87 = RES: RES MF 47K  1/16W 1% 0402; AGILE_PN: 470-31023; CAD_APPROVED: Yes; FPLIST: RC0402_25,RC0402_HD,RC0402_X2,0402_CC; HEIGHT: 0.40; MFG_NAME01: VISHAY; MFG_PN01: CRCW040247K0FKEDC; ROHS: Yes; Temp Range: –55 °C to +155 °C; Temp_Range: -55&#8451; to 155&#8451;; Tolerance: 1%
R91 = RES: RES MF 20K 1/16W 5% 0402; AGILE_PN: 470-76086; ASSY_OPT: DNP; CAD_APPROVED: Yes; FPLIST: RC0402_25,RC0402_HD,0402_CC; HEIGHT: 0.4; MFG_NAME01: BOURNS; MFG_PN01: CR0402-JW-203GLF; ROHS: Yes; Tolerance: 5%
R93 = RES: RES MF 10K 1/16W 5% 0402; AGILE_PN: 470-75557; ASSY_OPT: DNP; CAD_APPROVED: Yes; FPLIST: RC0402_25,RC0402_HD,0402_CC; HEIGHT: 0.4; MFG_NAME01: BOURNS; MFG_PN01: CR0402-JW-103GLF; ROHS: NULL; Tolerance: 5%
R94 = RES: RES MF 100K 1/16W 1% 0402; AGILE_PN: 470-76240; CAD_APPROVED: Yes; FPLIST: RC0402_25,RC0402_HD,0402_CC; HEIGHT: 0.4; MFG_NAME01: NIC COMPONENTS CORP; MFG_PN01: NRCL04F1003TRF; ROHS: Yes; Tolerance: 1%
R257 R265 = RES: RES MF 10K 1/16W 5% 0402; AGILE_PN: 470-75557; CAD_APPROVED: Yes; FPLIST: RC0402_25,RC0402_HD,0402_CC; HEIGHT: 0.4; MFG_NAME01: BOURNS; MFG_PN01: CR0402-JW-103GLF; ROHS: NULL; TOL: 5%; Tolerance: 5%
R294 = RES: RES MF 10K 1/16W 5% 0402; AGILE_PN: 470-75557; ASSY_OPT: DNP; CAD_APPROVED: Yes; FPLIST: RC0402_25,RC0402_HD,0402_CC; HEIGHT: 0.4; MFG_NAME01: BOURNS; MFG_PN01: CR0402-JW-103GLF; ROHS: NULL; TOL: 5%; Tolerance: 5%
R297 = RES_3PIN: RES MF ZERO OHM 1/10W -- 0402; AGILE_PN: 470-79965; ASSY_OPT: DNP; CAD_APPROVED: Yes; FPLIST: RC0402_25,RC0402_HD,RC0402_X2,0402_CC,RC0402_X3; HEIGHT: 0.4; MFG_NAME01: PANASONIC; MFG_PN01: ERJ-2GE0R00X; ROHS: Yes; Temp Range: –55 °C to +155 °C
U4 = NX5P3090UK_WLCSP12: IC USB PD TYPE C CURRENT LIMITED PWR SW 2.5-5.5V WLCSP12; 3D_Mechanical_Footprint_File: http://fcl.am.freescale.net/ALLEGRO/step/wlcsp12_0p4_1p38x1p68mm_smdp.STEP; AGILE_PN: 312-81574; CAD_APPROVED: Yes; HEIGHT: 0.565; MFG_NAME01: NXP SEMICONDUCTORS; MFG_PN01: NX5P3090UK,012; ROHS: Yes
U5 = RCLAMP1654P_NEW: DIODE TVS ARRAY 3 5.5V SLP1616P6; 3D_Mechanical_Footprint_File: http://fcl.am.freescale.net/ALLEGRO/step/slp1616p6.step; AGILE_PN: 480-78843; CAD_APPROVED: Yes; HEIGHT: 0.65; MFG_NAME01: SEMTECH CORP; ROHS: Yes; Rated Voltage: 5.5V; VOLTAGE: 5.5V
U41 = PTN5150A_X2QFN12: IC CC LOGIC USB TYPE-C 2.7-5.5V X2QFN12; 3D_Mechanical_Footprint_File: http://fcl.am.freescale.net/ALLEGRO/step/x2qfn12_0p4_1p6x1p6.STEP; AGILE_PN: 312-81473; CAD_APPROVED: Yes; HEIGHT: 0.4; MFG_NAME01: NXP SEMICONDUCTORS; MFG_PN01: PTN5150AHXMP; ROHS: Yes; VOLTAGE: 2.7-5.5V

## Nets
AGND: C9.2 C29.2 C31.2 R64.2 U1.R6(VREFL) ; also on sheet 12
GND: C1.2 C2.2 C3.2 C4.2 C5.2 C6.2 C7.2 C8.2 C10.2 C11.2 C12.2 C13.2 C14.2 C15.2 C16.2 C17.2 C18.2 C19.2 C20.2 C21.2 C22.2 C23.2 C24.2 C25.2 C26.2 C27.2 C28.2 C30.2 C32.2 C33.2 C34.2 C35.2 C36.2 C38.2 C39.2 C40.2 C41.2 C150.2 C154.2 D3.C(CATHODE) J11.A1(GND1) J11.A12(GND2) J11.B1(GND4) J11.B12(GND3) J11.SH1 J11.SH2 J11.SH3 J11.SH4 J16.1 J17.1 Q1.1(SOURCE) R64.1 R86.2 R91.2 R93.2 R94.2 R297.3 U1.D6(VSS_2) U1.D9(VSS_3) U1.D12(VSS_1) U1.E5(VSS_5) U1.E13(VSS_4) U1.G2(VSS_6) U1.H5(VSS_8) U1.H9(VSS_9) U1.H13(VSS_7) U1.J4(VSS_12) U1.J8(VSS_13) U1.J10(VSS_10) U1.J14(VSS_11) U1.K9(VSS_14) U1.N13(VSS_15) U1.P6(VSS_P4_1) U1.P7(VSS_P4_2) U1.P9(VSS_P4_3) U1.P12(VSS_18) U1.P14(VSS_16) U1.P16(VSS_DCDC) U1.T16(VSS_17) U2.2(VSS) U3.1(GND) U4.B3(GND1) U4.C3(GND2) U4.D3(GND3) U5.7(GND) U41.10(GND) ; also on sheet 7 8 9 10 11 12
P3V3_MCU: JP2.1 JP3.2 JP4.2 R71.2 R72.1 R73.1
P5V0: C1.1 C2.1 C5.1 C6.1 C7.1 C38.1 C39.1 D1.C D2.C D4.C TP2.1(Pin1) U2.1(CE) U2.4(VIN) U3.3(VIN) U4.B1(VINT1) U4.B2(VINT2) U4.C1(VINT3) ; also on sheet 11 12
P5V_HDR_IN: D4.A ; also on sheet 12
P5V_MCU_LINK_USB: D2.A ; also on sheet 8
P5V_USB_HS: C40.1 D1.A L3.2 TP14.1(Pin1)
VDD_1V8: C8.1 J20.1 U3.2(VOUT) ; also on sheet 7
VDD_BOARD: C154.1 JP1.1 R6.1 R7.1 R43.1 R44.1 R69.2 R87.1 R90.1 R257.1 R265.1 R278.1 R294.1 R297.1 TP24.1(Pin1) U41.12(VDD) ; also on sheet 7 8 9 10 11 12
VDD_CORE: C15.1 C18.1 C19.1 R83.1 R84.2 TP19.1(Pin1) U1.K10(VDD_CORE_1) U1.L11(VDD_CORE_2)
VDD_DCDC: C32.1 R79.2 R80.1 TP25.1(Pin1) U1.R15(VDD_DCDC)
VDD_LDO_CORE_IN: C35.1 R84.1 R85.2 TP26.1(Pin1) U1.K6(VDD_LDO_CORE)
VDD_LDO_SYS_IN: C30.1 R78.2 R82.1 TP27.1(Pin1) U1.P15(VDD_LDO_SYS)
VDD_MCU: C24.1 C25.1 C26.1 C27.1 JP3.1 R24.1 R72.2 R74.1 R75.1 R76.1 R77.1 R78.1 R79.1 R85.1 TP28.1(Pin1) U1.G7(VDD_2) U1.H6(VDD_1) U1.H8(VDD_3)
VDD_P2: C21.1 C22.1 C23.1 R77.2 TP29.1(Pin1) U1.K8(VDD_P2_1) U1.L7(VDD_P2_2)
VDD_P3: C13.1 C14.1 C16.1 C17.1 R75.2 TP30.1(Pin1) U1.G11(VDD_P3_1) U1.H10(VDD_P3_2) U1.H12(VDD_P3_3)
VDD_P4: C10.1 C11.1 C12.1 R74.2 TP31.1(Pin1) U1.N5(VDD_P4_1) U1.P4(VDD_P4_2)
VDD_SYS: C28.1 R82.2 TP20.1(Pin1) U1.N14(VDD_SYS)
VDD_USB: C33.1 R24.2 U1.R12(VDD_USB)
VDD_VBAT: C20.1 R76.2 TP32.1(Pin1) U1.T17(VDD_BAT)
VDDA_MCU: C9.1 C31.1 L1.2 R23.1 U1.R5(VREFH) ; also on sheet 12
ANA_7/VREFO: C29.1 U1.U4(ANA_7/VREFI/VREFO/ADC0_A7/ADC1_A7) ; also on sheet 12
DCDC_LX: L2.1 R81.2 U1.P17(DCDC_LX)
DCDC_VDD_CORE: C34.1 L2.2 R83.2 TP11.1(Pin1)
LDO_3V3: J15.1 JP1.2 JP2.2 R8.2 R69.1 R70.1 R71.1
MCU_HS_USB1_DM: J11.A7(DN1) J11.B7(DN2) L4.1 U5.1(DM)
MCU_HS_USB1_DP: J11.A6(DP1) J11.B6(DP2) L4.4 U5.2(DP)
MCU_LINK_RX: R53.1 R55.1 ; also on sheet 8
MCU_RESET_B: U1.F3(RESET_B) ; also on sheet 9 10 12
MCU_UART_RX: R54.1 R56.1 ; also on sheet 9
MCU_USB1_DM: L4.2 U1.R14(USB1_DM)
MCU_USB1_DP: L4.3 U1.R13(USB1_DP)
P0_0/SWDIO: U1.A17(P0_0/TMS/SWDIO/FC1_P0/CT_INP0) ; also on sheet 9
P0_1/SWCLK: U1.A16(P0_1/TCLK/SWCLK/FC1_P1/CT_INP1) ; also on sheet 9
P0_2/SWO: U1.B16(P0_2/TDO/SWO/FC1_P2/CT0_MAT0/UTICK_CAP0/I3C0_PUR) ; also on sheet 9
P0_3/TDI: U1.B15(P0_3/CMP1_IN1/TDI/FC1_P3/CT0_MAT1/UTICK_CAP1/HSCMP0_OUT) ; also on sheet 9
P0_4/SmartDMA_CAMERA_VSYNC: U1.B14(P0_4/EWM0_IN/FC0_P0/FC1_P4/CT0_MAT2/UTICK_CAP2/HSCMP1_OUT/PDM0_CLK) ; also on sheet 12
P0_5/SmartDMA_CAMERA_HSYNC: U1.A14(P0_5/EWM0_OUT_B/FC0_P1/FC1_P5/CT0_MAT3/UTICK_CAP3/PDM0_DATA0) ; also on sheet 12
P0_6: R2.1 U1.C14(P0_6/ISPMODE_N/FC0_P2/FC1_P6/CT_INP2/PDM0_DATA1/CLKOUT) ; also on sheet 9
P0_6/ISPMODE_N-SW: R2.2 ; also on sheet 10
P0_7/SmartDMA_CAMERA_PCLK: U1.C13(P0_7/FC0_P3/CT_INP3) ; also on sheet 12
P0_14/FXIO_D6: U1.E11(P0_14/ADC0_B14/FC1_P6/FC0_P2/CT_INP2/UTICK_CAP0/FLEXIO0_D6) ; also on sheet 12
P0_15/FXIO_D7: U1.G13(P0_15/ADC0_B15/FC0_P3/CT_INP3/UTICK_CAP1/FLEXIO0_D7) ; also on sheet 12
P0_16: R5.1 U1.B10(P0_16/ADC0_A8/FC0_P0/CT0_MAT0/UTICK_CAP2/FLEXIO0_D0/PDM0_CLK/I3C0_SDA) ; also on sheet 9
P0_16/PDM0_CLK-DMIC: R5.2 ; also on sheet 7 12
P0_17: R4.1 U1.A10(P0_17/ADC0_A9/FC0_P1/CT0_MAT1/UTICK_CAP3/FLEXIO0_D1/PDM0_DATA0/I3C0_SCL) ; also on sheet 9
P0_17/PDM0_DATA0-DMIC: R4.2 ; also on sheet 7 12
P0_18: U1.C10(P0_18/ADC0_A10/EWM0_IN/FC0_P2/CT0_MAT2/FLEXIO0_D2/HSCMP0_OUT/PDM0_DATA1) ; also on sheet 12
P0_19/GPIO: U1.C9(P0_19/ADC0_A11/EWM0_OUT_B/FC0_P3/CT0_MAT3/FLEXIO0_D3/HSCMP1_OUT) ; also on sheet 12
P0_20: R12.1 U1.C8(P0_20/ADC0_A12/FC0_P4/FC1_P0/CT_INP0/FLEXIO0_D4/I3C0_SDA) ; also on sheet 12
P0_20/WUU0_IN4-SW: R12.2 ; also on sheet 10
P0_21: R13.1 U1.A8(P0_21/ADC0_A13/FC0_P5/FC1_P1/CT_INP1/FLEXIO0_D5/I3C0_SCL) ; also on sheet 12
P0_21/ACCL_INT1: R13.2 ; also on sheet 11
P0_22: U1.B8(P0_22/ADC0_A14/CMP1_IN2/EWM0_IN/FC0_P6/FC1_P2/CT_INP2/FLEXIO0_D6/I3C0_PUR) ; also on sheet 12
P0_23: R18.1 U1.B7(P0_23/ADC0_A15/EWM0_OUT_B/FC1_P3/CT_INP3/FLEXIO0_D7) ; also on sheet 12
P0_23/ACCL_WAKEUP: R18.2 ; also on sheet 11
P0_24: R14.1 U1.B6(P0_24/ADC0_B16/FC1_P0/CT0_MAT0) ; also on sheet 12
P0_24/ACCL_INT2: R14.2 ; also on sheet 11
P0_25/ADC0_B17-LIGHT_SENSOR: U1.A6(P0_25/ADC0_B17/FC1_P1/CT0_MAT1) ; also on sheet 11 12
P0_26/ADC0_B18-MC_VOLT_DCB: U1.F10(P0_26/ADC0_B18/FC1_P2/CT0_MAT2) ; also on sheet 12
P0_27/ADC0_B19-MC_BEMF_C: U1.E10(P0_27/ADC0_B19/FC1_P3/CT0_MAT3) ; also on sheet 12
P0_28/ADC0_B20-MC_BEMF_B: U1.E8(P0_28/ADC0_B20/FC1_P4/FC0_P4/CT_INP0) ; also on sheet 12
P0_29/ADC0_B21-MC_BEMF_A: U1.F8(P0_29/ADC0_B21/FC1_P5/FC0_P5/CT_INP1) ; also on sheet 12
P1_0: R15.1 U1.C6(P1_0/ADC0_A16/CMP0_IN0/TRIG_IN0/FC3_P0/FC4_P4/CT_INP4/FLEXIO0_D8/SAI1_TX_BCLK) ; also on sheet 9 12
P1_0/FC3_SPI_SDO-ARD_D11: R15.2 ; also on sheet 12
P1_1: U1.C5(P1_1/ADC0_A17/CMP1_IN0/TRIG_IN1/FC3_P1/FC4_P5/CT_INP5/FLEXIO0_D9/SAI1_TX_FS) ; also on sheet 9 12
P1_2: U1.C4(P1_2/ADC0_A18/TRIG_OUT0/FC3_P2/FC4_P6/CT1_MAT0/FLEXIO0_D10/SAI1_TXD0/CAN0_TXD) ; also on sheet 9 12
P1_3: U1.B4(P1_3/ADC0_A19/CMP0_IN1/TRIG_OUT1/FC3_P3/CT1_MAT1/FLEXIO0_D11/SAI1_RXD0/CAN0_RXD) ; also on sheet 9 12
P1_4/SmartDMA_PIO0-CAMERA_D0: U1.A4(P1_4/ADC0_A20/CMP0_IN2/FREQME_CLK_IN0/FC3_P4/FC5_P0/CT1_MAT2/FLEXIO0_D12/SMARTDMA_PIO0/SAI0_TXD1) ; also on sheet 12
P1_5/SmartDMA_PIO1-CAMERA_D1: U1.B3(P1_5/ADC0_A21/CMP0_IN3/FREQME_CLK_IN1/FC3_P5/FC5_P1/CT1_MAT3/FLEXIO0_D13/SMARTDMA_PIO1/SAI0_RXD1) ; also on sheet 12
P1_6/SmartDMA_PIO2-CAMERA_D2: U1.B2(P1_6/ADC0_A22/TRIG_IN2/FC3_P6/FC5_P2/CT_INP6/FLEXIO0_D14/SMARTDMA_PIO2/SAI1_RX_BCLK/CAN1_TXD) ; also on sheet 12
P1_7: R22.1 U1.A2(P1_7/ADC0_A23/TRIG_OUT2/FC5_P3/CT_INP7/FLEXIO0_D15/SMARTDMA_PIO3/SAI1_RX_FS/CAN1_RXD) ; also on sheet 12
P1_7/SAI1_RX_FS: R22.2 ; also on sheet 12
P1_8: R54.2 U1.A1(P1_8/ADC1_A8/TRACE_DATA0/FC4_P0/FC5_P4/CT_INP8/FLEXIO0_D16/SMARTDMA_PIO4/I3C1_SDA) ; also on sheet 12
P1_9: R53.2 U1.B1(P1_9/ADC1_A9/TRACE_DATA1/FC4_P1/FC5_P5/CT_INP9/FLEXIO0_D17/SMARTDMA_PIO5/I3C1_SCL) ; also on sheet 12
P1_10/SmartDMA_PIO6-CAMERA_D6: U1.C3(P1_10/ADC1_A10/TRACE_DATA2/FC4_P2/FC5_P6/CT2_MAT0/FLEXIO0_D18/SMARTDMA_PIO6/CAN0_TXD) ; also on sheet 12
P1_11/SmartDMA_PIO7-CAMERA_D7: U1.D3(P1_11/ADC1_A11/TRACE_DATA3/FC4_P3/CT2_MAT1/FLEXIO0_D19/SMARTDMA_PIO7/I3C1_PUR/CAN0_RXD) ; also on sheet 12
P1_12/SmartDMA_PIO8: U1.D2(P1_12/ADC1_A12/TRACE_CLK/FC4_P4/FC3_P0/CT2_MAT2/FLEXIO0_D20/SMARTDMA_PIO8/CAN1_RXD) ; also on sheet 12
P1_13/SmartDMA_PIO9: U1.D1(P1_13/ADC1_A13/TRIG_IN3/FC4_P5/FC3_P1/CT2_MAT3/FLEXIO0_D21/SMARTDMA_PIO9/CAN1_TXD) ; also on sheet 12
P1_14/SmartDMA_PIO10: U1.D4(P1_14/ADC1_A14/FC4_P6/FC3_P2/CT_INP10/FLEXIO0_D22/SMARTDMA_PIO10) ; also on sheet 12
P1_15/SmartDMA_PIO11: U1.E4(P1_15/ADC1_A15/FC3_P3/CT_INP11/FLEXIO0_D23/SMARTDMA_PIO11/I3C1_PUR) ; also on sheet 12
P1_16: R39.1 U1.F6(P1_16/ADC1_A16/FC5_P0/FC3_P4/CT_INP12/FLEXIO0_D24/SMARTDMA_PIO12/I3C1_SDA) ; also on sheet 12
P1_16/FC5_I2C_SDA-ARD_D18: R6.2 R39.2 ; also on sheet 12
P1_17: R40.1 U1.F4(P1_17/ADC1_A17/FC5_P1/FC3_P5/CT_INP13/FLEXIO0_D25/SMARTDMA_PIO13/I3C1_SCL) ; also on sheet 12
P1_17/FC5_I2C_SCL-ARD_D19: R7.2 R40.2 ; also on sheet 12
P1_18/SmartDMA_PIO14-CAMERA_PDOWN: U1.G4(P1_18/ADC1_A18/FREQME_CLK_IN0/FC5_P2/FC3_P6/CT3_MAT0/FLEXIO0_D26/SMARTDMA_PIO14/CAN0_TXD) ; also on sheet 12
P1_19/SmartDMA_PIO15-CAMERA_RST: U1.G5(P1_19/ADC1_A19/FREQME_CLK_IN1/FC5_P3/CT3_MAT1/FLEXIO0_D27/SMARTDMA_PIO15/CAN0_RXD) ; also on sheet 12
P1_30/XTAL48M: U1.F1(P1_30/XTAL48M/TRIG_OUT3/CT_INP16/SAI0_MCLK) ; also on sheet 10
P1_31/EXTAL48M: U1.F2(P1_31/EXTAL48M/TRIG_IN4/CT_INP17) ; also on sheet 10
P2_0: U1.H2(P2_0/TRIG_IN5/PWM1_A3/FLEXIO0_D8/SMARTDMA_PIO20/SAI0_RX_BCLK) ; also on sheet 12
P2_1/GPIO: U1.H1(P2_1/TRACE_CLK/PWM1_B3/FLEXIO0_D9/SMARTDMA_PIO21/SAI0_RX_FS) ; also on sheet 12
P2_2/CLKOUT-SmartDMA_CAMERA_CLKIN: U1.H3(P2_2/CLKOUT/PWM1_A2/FLEXIO0_D10/SMARTDMA_PIO22/SAI0_TXD0) ; also on sheet 12
P2_3/FXIO_D11: U1.J3(P2_3/PWM1_B2/FLEXIO0_D11/SMARTDMA_PIO23/SAI0_RXD0) ; also on sheet 12
P2_4/FXIO_D12: U1.K3(P2_4/PWM1_A1/FLEXIO0_D12/SMARTDMA_PIO24/SAI0_RXD1) ; also on sheet 12
P2_5/FXIO_D13: U1.K1(P2_5/TRIG_OUT3/PWM1_B1/FLEXIO0_D13/SMARTDMA_PIO25/SAI0_TXD1) ; also on sheet 12
P2_6/FXIO_D14: U1.K2(P2_6/TRIG_IN4/PWM1_A0/FLEXIO0_D14/SMARTDMA_PIO26/SAI0_TX_BCLK) ; also on sheet 12
P2_7: U1.L2(P2_7/TRIG_IN5/PWM1_B0/FLEXIO0_D15/SMARTDMA_PIO27/SAI0_TX_FS) ; also on sheet 12
P2_8/SAI1_TXD0: U1.M2(P2_8/TRACE_DATA0/PWM1_X0/FLEXIO0_D16/SMARTDMA_PIO28/SAI1_TXD0) ; also on sheet 7 12
P2_9/SAI1_RXD0: U1.M1(P2_9/TRACE_DATA1/PWM1_X1/FLEXIO0_D17/SMARTDMA_PIO29/SAI1_RXD0) ; also on sheet 7 12
P2_10/SmartDMA_PIO31: U1.M3(P2_10/TRACE_DATA2/PWM1_X2/FLEXIO0_D18/SMARTDMA_PIO31/SAI1_RXD1) ; also on sheet 12
P2_11/SmartDMA_PIO30: U1.N4(P2_11/TRACE_DATA3/PWM1_X3/FLEXIO0_D19/SMARTDMA_PIO30/SAI1_TXD1) ; also on sheet 12
P3_0/FXIO_D8: U1.B17(P3_0/TRIG_IN0/FC7_P3/CT_INP16/PWM0_A0/FLEXIO0_D8/SMARTDMA_PIO0) ; also on sheet 12
P3_1/FXIO_D9: U1.C15(P3_1/TRIG_IN1/FC6_P0/FC7_P6/CT_INP17/PWM0_B0/FLEXIO0_D9/SMARTDMA_PIO1/FREQME_CLK_OUT0) ; also on sheet 12
P3_2/FXIO_D10: U1.D15(P3_2/FC7_P0/CT4_MAT0/PWM0_X0/FLEXIO0_D10/SMARTDMA_PIO2) ; also on sheet 12
P3_6/SAI1_MCLK: U1.D17(P3_6/CLKOUT/FC6_P1/CT4_MAT2/PWM0_A1/FLEXIO0_D14/SMARTDMA_PIO6/SAI1_MCLK/FREQME_CLK_OUT1) ; also on sheet 7 12
P3_7/FXIO_D15: U1.D14(P3_7/FC6_P6/FC7_P1/CT4_MAT3/PWM0_B1/FLEXIO0_D15/SMARTDMA_PIO7/SAI0_MCLK) ; also on sheet 12
P3_8/FXIO_D16: U1.E14(P3_8/FC6_P4/FC7_P0/CT_INP4/PWM0_A2/FLEXIO0_D16/SMARTDMA_PIO8/SAI0_TX_BCLK) ; also on sheet 12
P3_9/FXIO_D17: U1.F15(P3_9/FC6_P5/FC7_P2/CT_INP5/PWM0_B2/FLEXIO0_D17/SMARTDMA_PIO9/SAI0_TX_FS) ; also on sheet 12
P3_10/FXIO_D18: U1.F17(P3_10/FC6_P2/FC7_P4/CT1_MAT0/PWM0_A3/FLEXIO0_D18/SMARTDMA_PIO10/SAI0_TXD0) ; also on sheet 12
P3_11/FXIO_D19: U1.F16(P3_11/FC6_P3/FC7_P5/CT1_MAT1/PWM0_B3/FLEXIO0_D19/SMARTDMA_PIO11/SAI0_RXD0) ; also on sheet 12
P3_12: R35.1 R37.1 U1.G16(P3_12/FC7_P4/FC6_P4/CT1_MAT2/PWM1_A0/FLEXIO0_D20/SMARTDMA_PIO12/SAI0_RXD1)
P3_12/FC6_QSPI_D3: R35.2 ; also on sheet 11
P3_12/PWM1_A0: R37.2 ; also on sheet 12
P3_13: R36.1 U1.H16(P3_13/FC7_P5/FC6_P5/CT1_MAT3/PWM1_B0/FLEXIO0_D21/SMARTDMA_PIO13/SAI0_TXD1)
P3_13/FC6_QSPI_D2: R36.2 ; also on sheet 11
P3_14: U1.H17(P3_14/CT_INP6/PWM1_A1/FLEXIO0_D22/SMARTDMA_PIO14/SAI0_RX_BCLK) ; also on sheet 12
P3_15: U1.H15(P3_15/CT_INP7/PWM1_B1/FLEXIO0_D23/SMARTDMA_PIO15/SAI0_RX_FS) ; also on sheet 12
P3_16: U1.J15(P3_16/CT_INP8/PWM1_A2/FLEXIO0_D24/SMARTDMA_PIO16/SAI1_TX_BCLK) ; also on sheet 7 12
P3_17: U1.K15(P3_17/CT_INP9/PWM1_B2/FLEXIO0_D25/SMARTDMA_PIO17/SAI1_TX_FS) ; also on sheet 7 12
P3_18/SAI1_RX_BCLK: U1.K16(P3_18/FC6_P6/CT2_MAT0/PWM1_X0/FLEXIO0_D26/SMARTDMA_PIO18/SAI1_RX_BCLK) ; also on sheet 12
P3_20: R32.1 U1.M17(P3_20/TRIG_OUT0/FC6_P0/CT2_MAT2/PWM1_A3/FLEXIO0_D28/SMARTDMA_PIO20/SAI1_TXD0)
P3_20/FC6_QSPI_D0: R32.2 ; also on sheet 11
P3_21: R33.1 U1.L16(P3_21/TRIG_OUT1/FC6_P1/CT2_MAT3/PWM1_B3/FLEXIO0_D29/SMARTDMA_PIO21/SAI1_RXD0)
P3_21/FC6_QSPI_SCK: R33.2 ; also on sheet 11
P3_22: R34.1 U1.M16(P3_22/FC6_P2/CT_INP10/PWM1_X2/FLEXIO0_D30/SMARTDMA_PIO22/SAI1_RXD1)
P3_22/FC6_QSPI_D1: R34.2 ; also on sheet 11
P3_23: R31.1 U1.M15(P3_23/FC6_P3/CT_INP11/PWM1_X3/FLEXIO0_D31/SMARTDMA_PIO23/SAI1_TXD1)
P3_23/FC6_QSPI_CS0: R31.2 ; also on sheet 11
P4_0: R44.2 R49.1 R210.2 U1.P1(P4_0/ADC0_A0/TRIG_IN6/FC2_P0/CT_INP16/SMARTDMA_PIO24) ; also on sheet 7 12
P4_0/FC2_I2C_SDA-ACCL: R49.2 ; also on sheet 11
P4_1: R43.2 R50.1 R211.2 U1.P2(P4_1/ADC0_B0/TRIG_IN7/FC2_P1/CT_INP17/SMARTDMA_PIO25) ; also on sheet 7 12
P4_1/FC2_I2C_SCL-ACCL: R50.2 ; also on sheet 11
P4_2: R55.2 U1.T1(P4_2/ADC0_A4/ADC1_A4/CMP0_IN4N/CMP1_IN4N/TRIG_IN6/FC2_P2/CT_INP12/SMARTDMA_PIO26) ; also on sheet 12
P4_3: R56.2 U1.U1(P4_3/ADC0_B4/ADC1_B4/CMP0_IN5N/CMP1_IN5N/TRIG_IN7/FC2_P3/CT_INP13/SMARTDMA_PIO27) ; also on sheet 12
P4_4/SmartDMA_PIO28: U1.M6(P4_4/ADC1_A0/FC2_P4/CT_INP14/SMARTDMA_PIO28) ; also on sheet 12
P4_5/SmartDMA_PIO29: U1.M8(P4_5/ADC1_B0/FC2_P5/CT_INP15/SMARTDMA_PIO29) ; also on sheet 12
P4_6: U1.N7(P4_6/ADC0_A3/ADC1_A3/TRIG_OUT4/FC2_P6/CT_INP18/SMARTDMA_PIO30) ; also on sheet 12
P4_7/FXIO_LCD_RST: U1.T4(P4_7/CT_INP19/SMARTDMA_PIO31) ; also on sheet 12
P4_12/ARD_A4: U1.T6(P4_12/ADC0_A5/ADC1_A5/FC2_P0/CT4_MAT0/FLEXIO0_D20/CAN0_RXD) ; also on sheet 12
P4_13: R57.1 U1.T7(P4_13/ADC0_B5/ADC1_B5/TRIG_IN8/FC2_P1/USB1_OTGN_ID/CT4_MAT1/FLEXIO0_D21/CAN0_TXD) ; also on sheet 12
P4_13/TRIG_IN8-MC_ENC_B: R57.2 ; also on sheet 12
P4_14/FXIO_LCD_CS: U1.N8(P4_14/CT4_MAT2/FLEXIO0_D22) ; also on sheet 12
P4_15: R25.1 U1.T8(P4_15/ADC0_A1/CMP0_IN4P/TRIG_OUT4/USB1_VBUSVALID_EXT/CT4_MAT3/FLEXIO0_D23/CAN1_RXD) ; also on sheet 12
P4_15/CAN1_RXD: R25.2 ; also on sheet 11
P4_16: R67.1 R92.1 U1.R8(P4_16/ADC0_A6/FC2_P2/USB1_OTGN_PWR/CT3_MAT0/FLEXIO0_D24/CAN1_TXD) ; also on sheet 12
P4_16/CAN1_TXD: R67.2 ; also on sheet 11
P4_17: R88.1 U1.R9(P4_17/ADC0_B6/TRIG_IN9/FC2_P3/USB1_OTGN_OC/CT3_MAT1/FLEXIO0_D25) ; also on sheet 10 12
P4_18: U1.N10(P4_18/CT3_MAT2/FLEXIO0_D26) ; also on sheet 10 12
P4_19: U1.R10(P4_19/ADC0_B1/CMP1_IN4P/TRIG_OUT5/CT3_MAT3/FLEXIO0_D27) ; also on sheet 10 12
P4_20/FXIO_LCD_WR: U1.T10(P4_20/ADC1_A6/TRIG_IN8/FC2_P4/CT2_MAT0/FLEXIO0_D28) ; also on sheet 12
P4_21/TRIG_IN9-MC_ENC_A: U1.T11(P4_21/ADC1_B6/TRIG_IN9/FC2_P5/CT2_MAT1/FLEXIO0_D29) ; also on sheet 12
P4_22/FXIO_D30-CAMERA_PCLK: U1.T12(P4_22/CT2_MAT2/FLEXIO0_D30) ; also on sheet 12
P4_23/FXIO_LCD_TE: U1.U12(P4_23/ADC0_A2/ADC0_B2/ADC1_B3/TRIG_OUT5/FC2_P6/CT2_MAT3/FLEXIO0_D31) ; also on sheet 12
P5_0/EXTAL32K: U1.U16(P5_0/EXTAL32K/ADC1_B8/TRIG_IN10/LPTMR0_ALT2) ; also on sheet 10
P5_1/XTAL32K: U1.U17(P5_1/XTAL32K/ADC1_B9/TRIG_OUT6/LPTMR1_ALT2) ; also on sheet 10
P5_2/MIKROE_RESET: U1.M10(P5_2/ADC1_B10/VBAT_WAKEUP_B/SPC_LPREQ/TAMPER0) ; also on sheet 12
P5_3/ADC1_B11-MIKROE_AN: U1.N11(P5_3/ADC1_B11/TRIG_IN11/RTC_CLKOUT/TAMPER1) ; also on sheet 12
P5_4/PMOD_RESET: U1.M12(P5_4/ADC1_B12/TRIG_OUT7/SPC_LPREQ/TAMPER2) ; also on sheet 12
P5_5/PMOD_INT: U1.K12(P5_5/ADC1_B13/TRIG_IN10/LPTMR0_ALT2/TAMPER3) ; also on sheet 12
P5_6/MIKROE_INT: U1.K13(P5_6/ADC1_B14/TRIG_OUT6/LPTMR1_ALT2/TAMPER4) ; also on sheet 12
P5_7: R257.2 U1.L13(P5_7/ADC1_B15/TRIG_IN11/TAMPER5) U41.6(INTB/OUT3) ; also on sheet 12
USB1_CC1: J11.A5(CC1) U41.1(CC1)
USB1_CC2: J11.B5(CC2) U41.2(CC2)
USB1_ID: R93.1 R265.2 R295.1 U1.P11(USB1_ID) U5.3(USB_ID) U41.9(ID)
USB1_VBUS: R89.2 R91.1 TP15.1(Pin1) U1.U14(USB1_VBUS)
USB_OTG_VBUS: C36.1 C41.1 J11.A4(VBUS1) J11.A9(VBUS2) J11.B4(VBUS4) J11.B9(VBUS3) L3.1 R89.1 R276.2 TP16.1(Pin1) U4.C2(VBUS1) U4.D1(VBUS2) U4.D2(VBUS3) U5.6(VBUS)
N1489105: R87.2 R88.2 U4.A2(~{FAULT})
N1489467: Q1.3(DRAIN) R90.2 R92.2 U4.A1(EN)
N1489479: R94.1 U4.A3(ILIM)
N16628053: C3.1 C4.1 R8.1 U2.5(VOUT)
N16629904: D3.A(ANODE) R70.2
N16780586: JP4.1 L1.1 R73.2
N17362656: R278.2 U41.11(EXT_SEL)
N17362693: C150.1 R276.1 U41.4(VBUS_DET)
N17362702: R210.1 U41.7(SDA/OUT1)
N17362725: R211.1 U41.8(SCL/OUT2)
N17363203: R294.2 U41.5(ADR/CON_DET)
N17363355: R297.2 U41.3(PORT)
N17363759: Q1.2(GATE) R295.2
N17508182: R80.2 R81.1 R86.1
N17598018: R23.2 U1.R4(VDD_ANA)

Not connected (* = marked no-connect by the designer): BH1 1*; BH2 1*; BH3 1*; BH4 1*; J11 A8(SBU1)* B8(SBU2)*; U1 A12(NC_2)* B11(NC_4)* B12(NC_3)* C12(NC_1)* D7(NC_6)* D11(NC_27)* D16(NC_11)* E7(NC_5)* F12(NC_28)* F14(NC_12)* G14(NC_13)* K5(NC_7)* K17(NC_14)* L4(NC_9)* L5(NC_8)* L14(NC_15)* M4(NC_10)* M14(NC_16)* P3(NC_19)* R3(NC_20)* T2(NC_21)* T3(NC_22)* T14(NC_17)* T15(NC_18)* U2(NC_23)* U6(NC_24)* U8(NC_25)* U10(NC_26)*; U2 3(NC)*; U5 4(NC1)* 5(NC2)*

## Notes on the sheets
sheet 1
- FRDM-MCXN236
- REVISION HISTORY
- REVISION
- DESCRIPTION OF CHANGE
- DATE
- Approved
- 28-Apr-2023
- Jonson Chen
- X1
- Draft
- 20-June-2023
- Jonson Chen
- A
- Released A085
- B
- Reverse QSPI D2 and D3
  Change R276 from 1M to 0R
  Add 0R registers R23, R24 for VDD_ANA and VDD_USB wire
  Update the header index of MikroE, FlexIO, SmartDMA, PMOD interfaces
  Change the J2-18, J2-20 from P4_0/P4_1 to P1_16/P1_17,  add R6 and R7
  Change the buttons from 434153017835 to 434123025826
  Change ARD D2, D3, D5, D6, D9, D10, D11 from CTIMER to FlexPWM pins
  Remove DNP setting for resistors of MCU-Link SPI/I2C bridge
  Remove L5, L16, add R301,C157, R300, C155
  Add R8
- 14-Sep-2023
- Jonson Chen
- Table of Contents
- 01
- COVER
- 02
- BLOCK DIAGRAM
- 03
- MCU_PORT_0_1_2_3
- 04
- MCU_PORT_4_5_A
- 05
- B1
- DNP U6, J14, J21.
  Change C28 from 0.1uF to 2.2uF.
  Change C18 from 1.0uF to 4.7uF.
  Change C30 from 0.1uF to 1.0uF
- 24-Jan-2024
- Jonson Chen
- MCU_POWER
- 06
- USB
- 07
- AUDIO
- 08
- MCU_LINK_USB
- B2
- Upgrade to Rev B2 due to ARAS system issue, no design change.
- 26-Jan-2024
- Jonson Chen
- 09
- MCU_LINK_DEBUG
- Update signals of J8_6, J8_8.
  Delete C157, C155, R301, R300
  Change R89, R121 from 10K to 0R, DNP R91, R122
  Add TP10 - TP32 for automatic testing
- 10
- CLOCK_RESET_HMI
- C
- 25-Mar-2024
- Jonson Chen
- 11
- SENSOR_CAN_QSPI
- 12
- HEADERS
- 13
- APPENDIX JUMPER/DNP
sheet 2
- BLOCK DIAGRAM
sheet 5
- POWER
- Maximum Output Current : 700mA
- POWER LED
- SYS_5V0
- GND Test Points
- Power Supply Test Points
- Mounting Holes
- Note:
  The mechanical mounting holes are
  placed on the four vertices of the board
- Note:
  Two ground test points are placed
  on the left and right sides of the board to
  facilitate testing
- SOC POWER
- CAD note: Keep trace lengths short
  and components close to pins
- CAD note: Place inductor and cap close to MCU
- DCDC Inductor
- (Default) VDD_LDO Bypass: populate R79, R83, R84, DNP R80, R81, R85
            VDD_DCDC Bypass: populate  R80, R81, R85, DNP R79, R83, R84
- Populate only in LDO_SYS bypass mode.
sheet 6
- USB
- VBUS control
- USB1_OTG High Speed
- USB Type-C
- CAD note: 90Ohms differential impedance
- CC Logic Control
- EXT_SEL
- PORT
- ADR/CON_DET
- 0---CC2
    1---CC1
- PORT=1: DFP mode
  PORT=0: UFP mode
  PORT=Float: DRP mode
- CON_DET=1, Connection Detected, I2C Address: 0x7A
  CON_DET=0, No Connection, I2C Address: 0x3A
- Default
- 1
- Float
- Float, no I2C function
